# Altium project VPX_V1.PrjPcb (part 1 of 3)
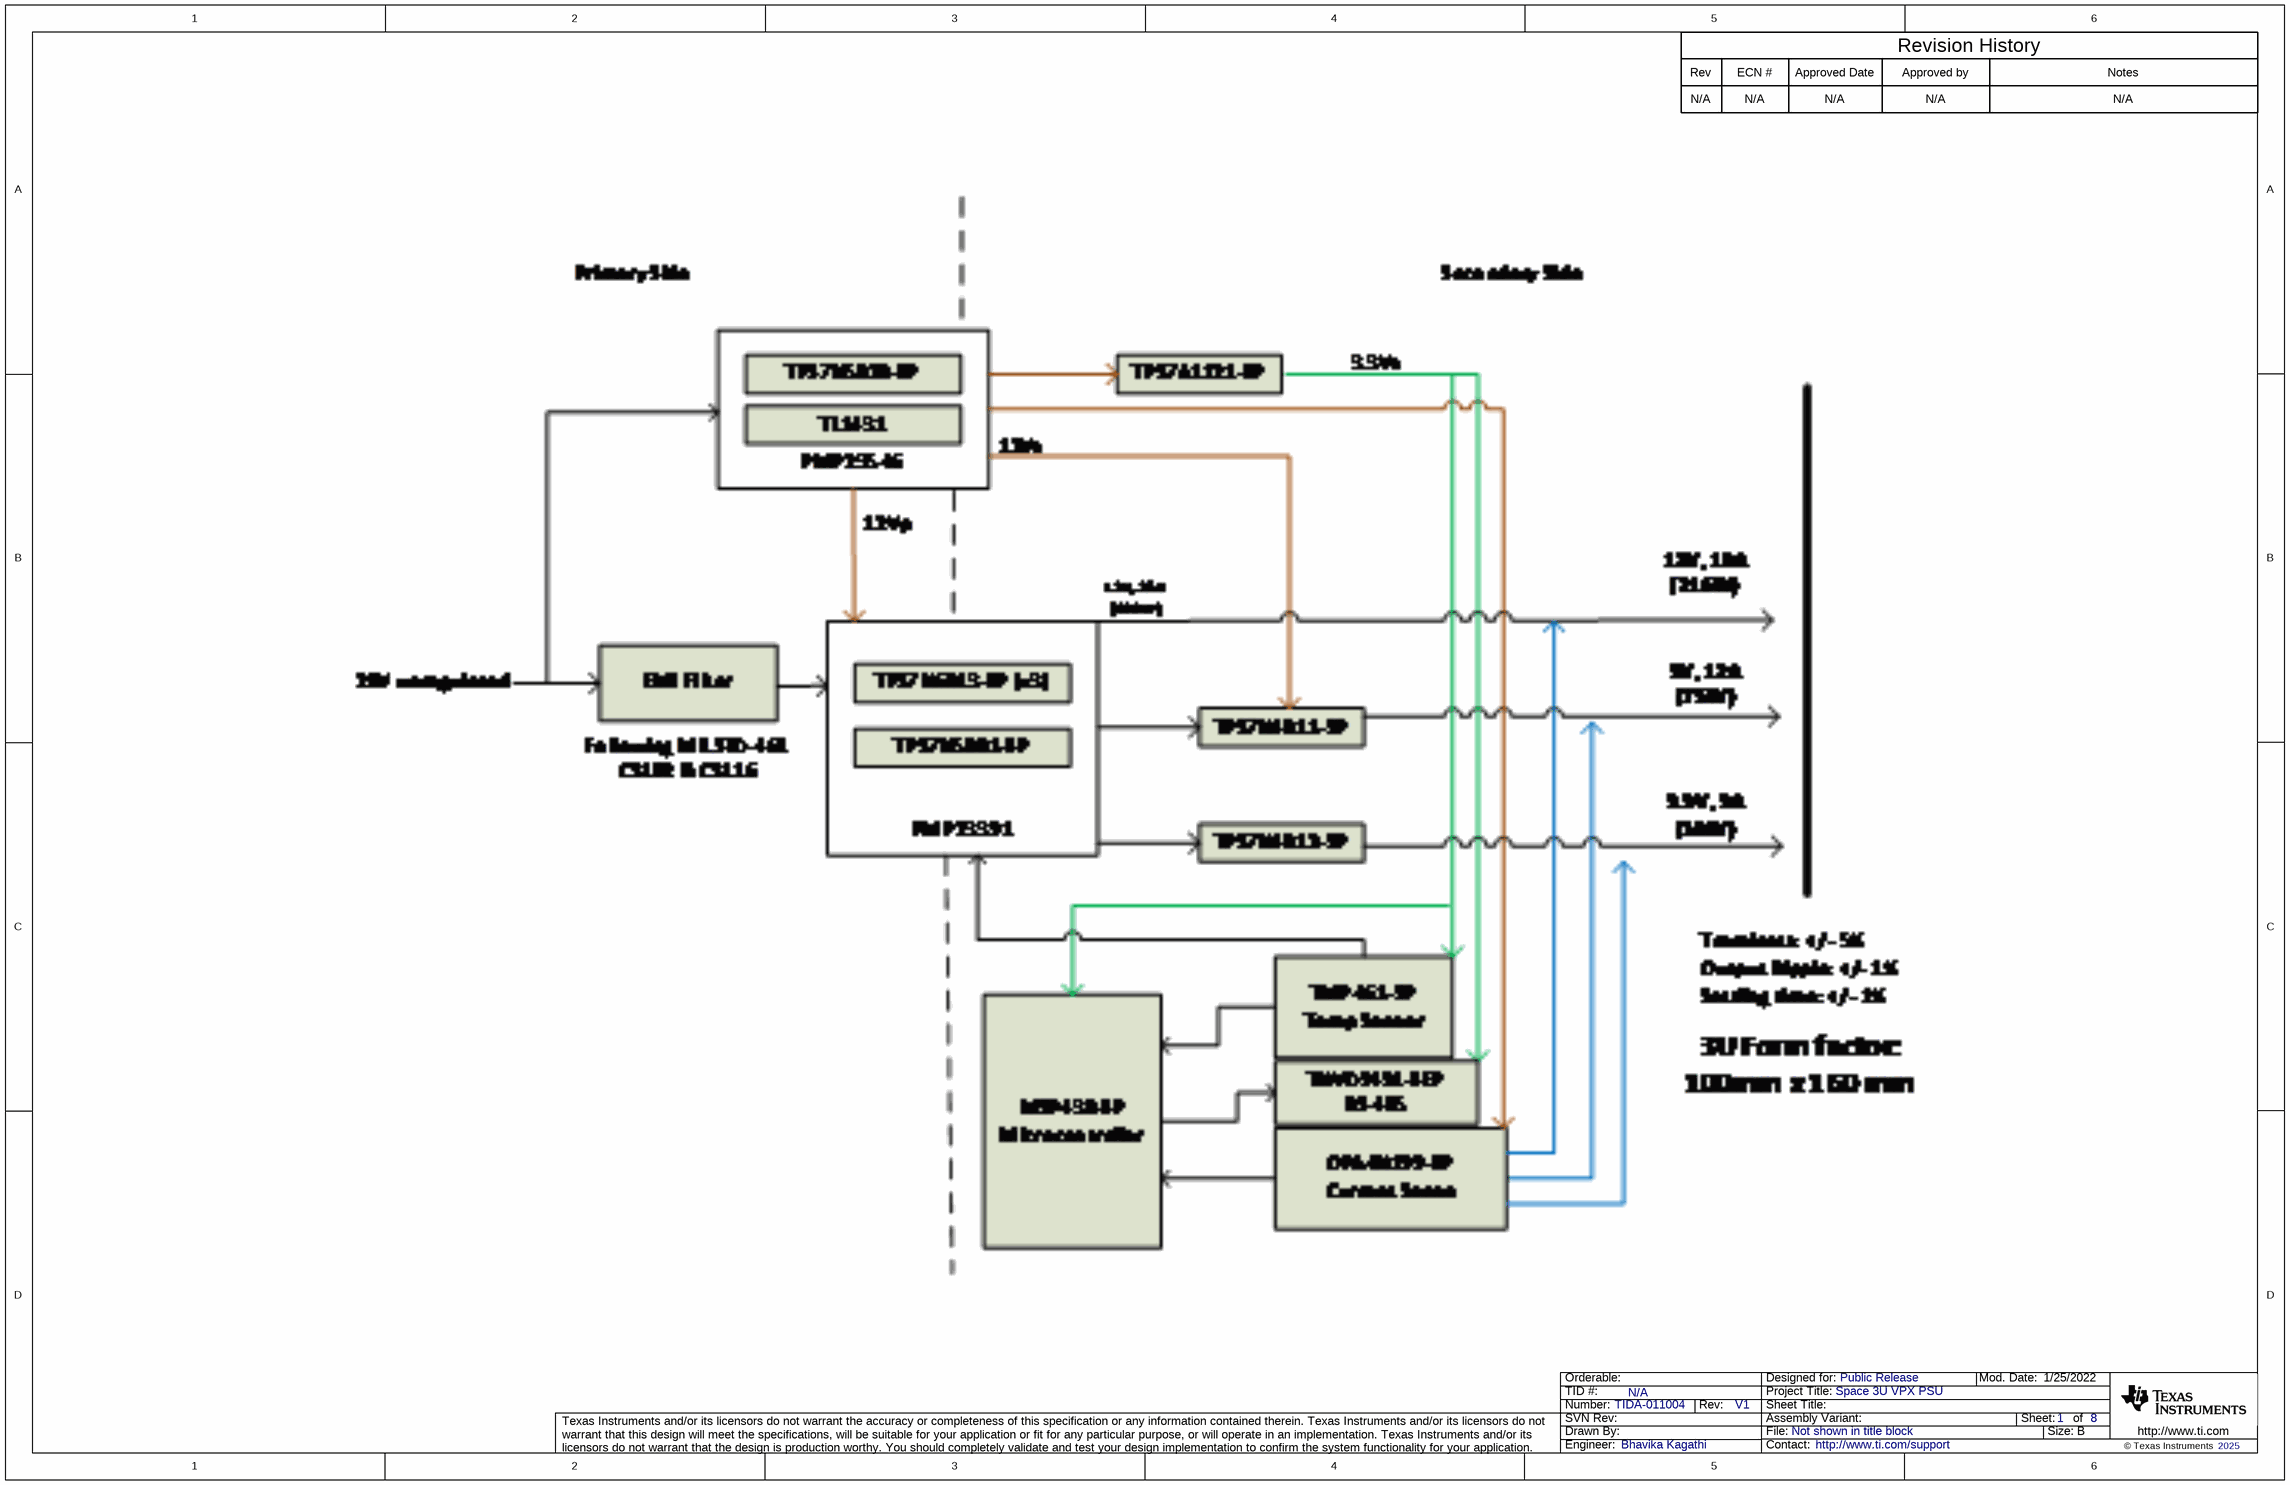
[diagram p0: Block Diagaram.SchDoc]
CopyrightYear: 2025; PCB_Rev: V1; PRJ_Customer: Public Release; PRJ_Engineer: Bhavika Kagathi; PRJ_Number: TIDA-011004; PRJ_Title: Space 3U VPX PSU; SCH_Rev: V1; Space 3U VPX PSU: Bhavika Kagathi; TechSupport: http://www.ti.com/support; TID: N/A
8 sheets, 383 parts. Net scope: flat (ports and power ports of the same name join across sheets).
Board file: VPX_V1.PcbDoc
Sheets:
  Block Diagaram.SchDoc
  12V Bias.SchDoc
  28V to 12 V.SchDoc
  28V to 12V drivers.SchDoc
  12V to 5V.SchDoc
  12 to 3.3V.SchDoc
  Telemetry.SchDoc
  Connector.SchDoc

## Sheet Block Diagaram.SchDoc
size 431 x 279 mm; Date: Not shown in title block; ApprovedBy: Not shown in title block; CheckedBy: Not shown in title block; Author: Not shown in title block; CompanyName: Not shown in title block; Engineer: Not shown in title block; Organization: Not shown in title block; Address1: Not shown in title block; Address2: Not shown in title block; Address3: Not shown in title block; Address4: Not shown in title block; DocumentNumber: 1; Revision: Use project parameter SCH_Rev; SheetNumber: 1; SheetTotal: 8; PageSetup: Record=PageOptions¦CenterHorizontal=True¦CenterVertical=True¦PrintScale=1.00¦XCorrection=1.00¦YCorrection=1.00¦PrintKind=0¦BorderSize=5000000¦LeftOffset=0¦BottomOffset=0¦Orientation=2¦PaperLength=1000¦PaperWidth=1000¦Scale=100¦PaperSource=15¦PrintQuality=600¦MediaType=1¦DitherType=10¦PaperKind=Letter¦PrintScaleMode=1

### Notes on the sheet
- Rev
- N/A
- ECN #
- Approved Date
- Approved by
- Revision History
- Notes

## Sheet 12V Bias.SchDoc
size 431 x 279 mm; Date: Not shown in title block; ApprovedBy: Not shown in title block; CheckedBy: Not shown in title block; Author: Not shown in title block; CompanyName: Not shown in title block; Engineer: Not shown in title block; Organization: Not shown in title block; Address1: Not shown in title block; Address2: Not shown in title block; Address3: Not shown in title block; Address4: Not shown in title block; DocumentNumber: 1; Revision: Use project parameter SCH_Rev; SheetNumber: 2; SheetTotal: 8; PageSetup: Record=PageOptions¦CenterHorizontal=True¦CenterVertical=True¦PrintScale=1.00¦XCorrection=1.00¦YCorrection=1.00¦PrintKind=0¦BorderSize=5000000¦LeftOffset=0¦BottomOffset=0¦Orientation=2¦PaperLength=1000¦PaperWidth=1000¦Scale=100¦PaperSource=15¦PrintQuality=600¦MediaType=1¦DitherType=10¦PaperKind=Letter¦PrintScaleMode=1
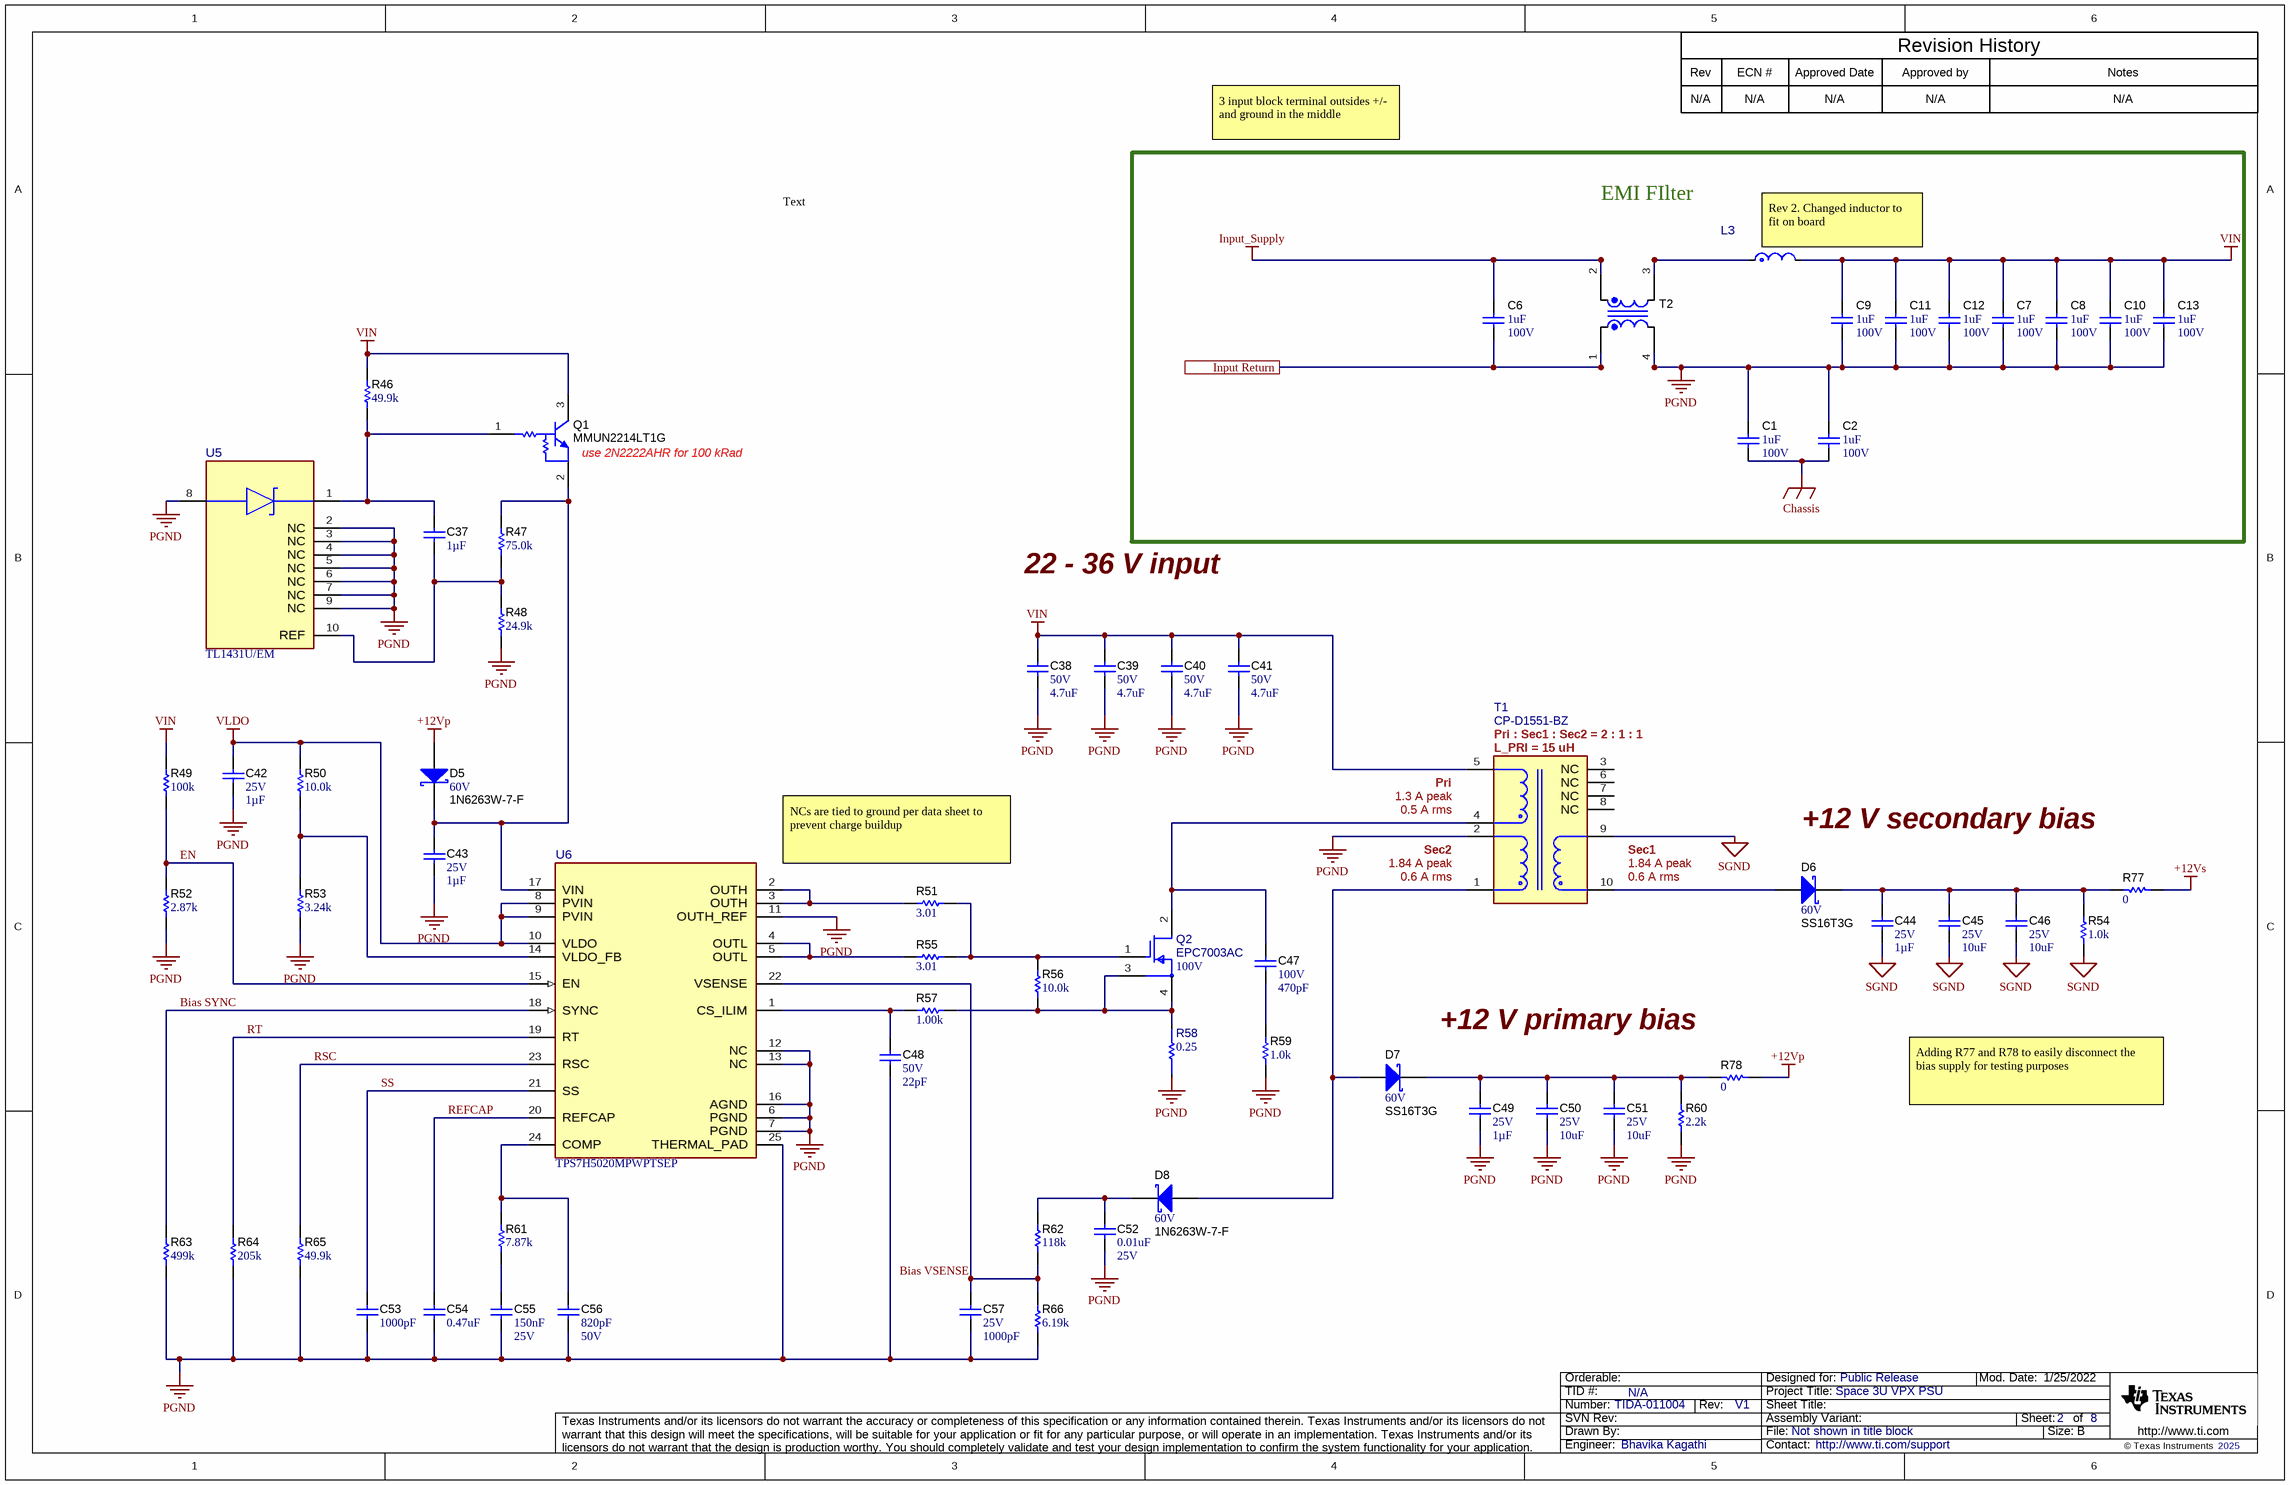
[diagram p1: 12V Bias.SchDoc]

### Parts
C1  ValueDisplayed: 1uF  VDC_V: 100V  [1210_270]  (hidden comment: GRM32ER72A105KA01L)
C2  ValueDisplayed: 1uF  VDC_V: 100V  [1210_270]  (hidden comment: GRM32ER72A105KA01L)
C6  ValueDisplayed: 1uF  VDC_V: 100V  [1210_270]  (hidden comment: GRM32ER72A105KA01L)
C7  ValueDisplayed: 1uF  VDC_V: 100V  [1210_270]  (hidden comment: GRM32ER72A105KA01L)
C8  ValueDisplayed: 1uF  VDC_V: 100V  [1210_270]  (hidden comment: GRM32ER72A105KA01L)
C9  ValueDisplayed: 1uF  VDC_V: 100V  [1210_270]  (hidden comment: GRM32ER72A105KA01L)
C10  ValueDisplayed: 1uF  VDC_V: 100V  [1210_270]  (hidden comment: GRM32ER72A105KA01L)
C11  ValueDisplayed: 1uF  VDC_V: 100V  [1210_270]  (hidden comment: GRM32ER72A105KA01L)
C12  ValueDisplayed: 1uF  VDC_V: 100V  [1210_270]  (hidden comment: GRM32ER72A105KA01L)
C13  ValueDisplayed: 1uF  VDC_V: 100V  [1210_270]  (hidden comment: GRM32ER72A105KA01L)
C37  Cap_F: 1µF  [0603]  (hidden comment: C0603C105K3RACTU)
C38  VDC_V: 50V  ValueDisplayed: 4.7uF  [0805_HV1]  (hidden comment: GRM21BR61H475KE51L)
C39  VDC_V: 50V  ValueDisplayed: 4.7uF  [0805_HV1]  (hidden comment: GRM21BR61H475KE51L)
C40  VDC_V: 50V  ValueDisplayed: 4.7uF  [0805_HV1]  (hidden comment: GRM21BR61H475KE51L)
C41  VDC_V: 50V  ValueDisplayed: 4.7uF  [0805_HV1]  (hidden comment: GRM21BR61H475KE51L)
C42  VDC_V: 25V  Cap_F: 1µF  [0603]  (hidden comment: C0603C105K3RACTU)
C43  VDC_V: 25V  Cap_F: 1µF  [0603]  (hidden comment: C0603C105K3RACTU)
C44  VDC_V: 25V  Cap_F: 1µF  [0603]  (hidden comment: C0603C105K3RACTU)
C45  VDC_V: 25V  ValueDisplayed: 10uF  [0805_HV1]  (hidden comment: GRM21BZ71E106KE15L)
C46  VDC_V: 25V  ValueDisplayed: 10uF  [0805_HV1]  (hidden comment: GRM21BZ71E106KE15L)
C47  VDC_V: 100V  ValueDisplayed: 470pF  [0603_HV]  (hidden comment: GRM1885C2A471JA01D)
C48  VDC_V: 50V  ValueDisplayed: 22pF  [0603_HV]  (hidden comment: GRM1885C1H220JA01D)
C49  VDC_V: 25V  Cap_F: 1µF  [0603]  (hidden comment: C0603C105K3RACTU)
C50  VDC_V: 25V  ValueDisplayed: 10uF  [0805_HV1]  (hidden comment: GRM21BZ71E106KE15L)
C51  VDC_V: 25V  ValueDisplayed: 10uF  [0805_HV1]  (hidden comment: GRM21BZ71E106KE15L)
C52  value 0.01uF  VDC_V: 25V  [0603_HV]  (hidden comment: GRM188R71E103KA01D)
C53  value 1000pF  [0603_HV]  (hidden comment: GRM188R71E102KA01D)
C54  value 0.47uF  [0603_HV]  (hidden comment: GCM188R71C474KA55D)
C55  Cap_F: 150nF  VDC_V: 25V  [0603_HV]  (hidden comment: GRM188R71E154KA01D)
C56  Cap_F: 820pF  VDC_V: 50V  [0603_HV]  (hidden comment: GRM188R71H821KA01D)
C57  value 1000pF  VDC_V: 25V  [0603_HV]  (hidden comment: GRM188R71E102KA01D)
D5  1N6263W-7-F  value 60V  [SOD-123]
D6  SS16T3G  value 60V  [SMA]
D7  SS16T3G  value 60V  [SMA]
D8  1N6263W-7-F  value 60V  [SOD-123]
L3  XGL1010-103MED  [FP-XGL1010-103MED_SMT_IND_10MM0_11MM3-MFG]  (value not drawn)
Q1  MMUN2214LT1G  [SOT-23]
Q2  EPC7003AC  VdsMax_V: 100V  [FP-EPC7003AC_FSMD-A-MFG]
R46  ValueDisplayed: 49.9k  [0603_HV]  (hidden comment: CRCW060349K9FKEA)
R47  ValueDisplayed: 75.0k  [0603_HV]  (hidden comment: CRCW060375K0FKEA)
R48  ValueDisplayed: 24.9k  [0603_HV]  (hidden comment: CRCW060324K9FKEA)
R49  ValueDisplayed: 100k  [0603_HV]  (hidden comment: CRCW0603100KFKEA)
R50  ValueDisplayed: 10.0k  [0603_HV]  (hidden comment: CRCW060310K0FKEA)
R51  ValueDisplayed: 3.01  [0603_HV]  (hidden comment: CRCW06033R01FKEA)
R52  ValueDisplayed: 2.87k  [0603_HV]  (hidden comment: CRCW06032K87FKEA)
R53  ValueDisplayed: 3.24k  [0603_HV]  (hidden comment: CRCW06033K24FKEA)
R54  ValueDisplayed: 1.0k  [1206]  (hidden comment: CRCW12061K00JNEA)
R55  ValueDisplayed: 3.01  [0603_HV]  (hidden comment: CRCW06033R01FKEA)
R56  ValueDisplayed: 10.0k  [0603_HV]  (hidden comment: CRCW060310K0FKEA)
R57  ValueDisplayed: 1.00k  [0603_HV]  (hidden comment: CRCW06031K00FKEA)
R58  ValueDisplayed: 0.25  [FP-CSR0805FKR250_0805-MFG]  (hidden comment: CSR0805FKR250)
R59  ValueDisplayed: 1.0k  [1210]  (hidden comment: RC1210JR-071KL)
R60  ValueDisplayed: 2.2k  [1206]  (hidden comment: CRCW12062K20JNEA)
R61  ValueDisplayed: 7.87k  [0603_HV]  (hidden comment: CRCW06037K87FKEA)
R62  ValueDisplayed: 118k  [0603_HV]  (hidden comment: CRCW0603118KFKEA)
R63  ValueDisplayed: 499k  [0603_HV]  (hidden comment: CRCW0603499KFKEA)
R64  ValueDisplayed: 205k  [0603_HV]  (hidden comment: CRCW0603205KFKEA)
R65  ValueDisplayed: 49.9k  [0603_HV]  (hidden comment: CRCW060349K9FKEA)
R66  ValueDisplayed: 6.19k  [0603_HV]  (hidden comment: CRCW06036K19FKEA)
R77  ValueDisplayed: 0  [0603_HV]  (hidden comment: CRCW06030000Z0EA)
R78  ValueDisplayed: 0  [0603_HV]  (hidden comment: CRCW06030000Z0EA)
T1  CP-D1551-BZ  [FP-CP-D1551-BZ_SMT_XFRMR_17MM75_14MM0-MFG]
T2  CM3440Z171R-10  [Laird_Z171R-10]  (value not drawn)
U5  TL1431U/EM  [NAC0010A-IPC_B]
U6  TPS7H5020MPWPTSEP  [PWP0024R-MFG]

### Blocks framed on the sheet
EMI FIlter: C1 C2 C6-C13 L3 T2

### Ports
Input Return

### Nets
+12Vp: D5.2(A) R78.2
+12Vs: R77.2
Chassis: C1.2 C2.2
Input_Supply: C6.1 T2.2
PGND: C1.1 C2.1 C7.2 C8.2 C9.2 C10.2 C11.2 C12.2 C13.2 C38.2 C39.2 C40.2 C41.2 C42.2 C43.2 C48.2 C49.2 C50.1 C51.1 C52.1 C53.1 C54.2 C55.2 C56.2 C57.1 R48.1 R52.1 R53.1 R58.1 R59.1 R60.1 R63.1 R64.1 R65.1 R66.1 T1.2 T2.4 U5.2(NC) U5.3(NC) U5.4(NC) U5.5(NC) U5.6(NC) U5.7(NC) U5.8(ANODE) U5.9(NC) U6.6(PGND) U6.7(PGND) U6.11(OUTH_REF) U6.12(NC) U6.13(NC) U6.16(AGND) U6.25(THERMAL_PAD)
SGND: C44.2 C45.1 C46.1 R54.1 T1.9
VIN: C7.1 C8.1 C9.1 C10.1 C11.1 C12.1 C13.1 C38.1 C39.1 C40.1 C41.1 L3.2 Q1.3(C) R46.2 R49.2 T1.5
VLDO: C42.1 R50.2 U6.8(PVIN) U6.9(PVIN) U6.10(VLDO)
Bias SYNC: R63.2 U6.18(SYNC)
Bias VSENSE: C57.2 R62.1 R66.2 U6.22(VSENSE)
EN: R49.1 R52.2 U6.15(EN)
Input Return: C6.2 T2.1 ; port Input Return
REFCAP: C54.1 U6.20(REFCAP)
RSC: R65.2 U6.23(RSC)
RT: R64.2 U6.19(RT)
SS: C53.2 U6.21(SS)
NetC37_1: C37.1 Q1.1(B) R46.1 U5.1(CATHODE)
NetC37_2: C37.2 R47.1 R48.2 U5.10(REF)
NetC43_1: C43.1 D5.1(K) Q1.2(E) R47.2 U6.17(VIN)
NetC44_1: C44.1 C45.2 C46.2 D6.1(K) R54.2 R77.1
NetC47_1: C47.1 Q2.2(D) T1.4
NetC47_2: C47.2 R59.2
NetC48_1: C48.1 R57.2 U6.1(CS_ILIM)
NetC49_1: C49.1 C50.2 C51.2 D7.1(K) R60.2 R78.1
NetC52_2: C52.2 D8.1(K) R62.2
NetC55_1: C55.1 R61.1
NetC56_1: C56.1 R61.2 U6.24(COMP)
NetD6_2: D6.2(A) T1.10
NetD7_2: D7.2(A) D8.2(A) T1.1
NetL3_1: L3.1 T2.3
NetQ2_1: Q2.1(G) R51.2 R55.2 R56.2
NetQ2_3: Q2.3(SS) Q2.4(S) R56.1 R57.1 R58.2
NetR50_1: R50.1 R53.2 U6.14(VLDO_FB)
NetR51_1: R51.1 U6.2(OUTH) U6.3(OUTH)
NetR55_1: R55.1 U6.4(OUTL) U6.5(OUTL)

Not connected (* = marked no-connect by the designer): T1 3(NC) 6(NC) 7(NC) 8(NC)

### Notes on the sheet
- Rev
- N/A
- ECN #
- Approved Date
- Approved by
- Revision History
- Notes
- 3 input block terminal outsides +/- and ground in the middle
- (near L3) Rev 2. Changed inductor to fit on board
- Text
- (near Q1) use 2N2222AHR for 100 kRad
- 22 - 36 V input
- (near T1) L_PRI = 15 uH
- (near T1) Pri : Sec1 : Sec2 = 2 : 1 : 1
- (near T1) Pri
- (near T1) 1.3 A peak
- (near T1) 0.5 A rms
- +12 V secondary bias
- NCs are tied to ground per data sheet to prevent charge buildup
- (near T1) Sec2
- (near T1) 1.84 A peak
- (near T1) 0.6 A rms
- (near T1) Sec1
- +12 V primary bias
- Adding R77 and R78 to easily disconnect the bias supply for testing purposes

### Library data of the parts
C1 C2 C6-C13 = CMP-0009231-2: CAP, CERM, 1 uF, 100 V, +/- 10%, X7R, 1210; Manufacturer: MuRata; Cap_F: 1µF; Value: 1uF; SizeZ_mm: 2.7; TaMin_C: -55°C; Polarized: N; SizeAreaWB_mm2: 14.7; Value1: Unknown; U/M: EA; TaMax_C: 125°C; SizeX_mm: 3.2; SizeY_mm: 2.5; Cap_Case: 1210; SizeArea_mm2: 8; AEC Category: Q200
C37 = CMP-0006867-4: CAP, CERM, 1 uF, 25 V, +/- 10%, X7R, 0603; Manufacturer: Kemet; VDC_V: 25V; AEC Category: Q200; Value: 1uF; SizeX_mm: 1.6; U/M: EA; Value1: Unknown; SizeAreaWB_mm2: 4.68; SizeY_mm: 0.8; TaMin_C: -55°C; SizeZ_mm: 1; Polarized: N; TaMax_C: 125°C; SizeArea_mm2: 1.28
C38-C41 = CMP-0008309-2: CAP, CERM, 4.7 uF, 50 V, +/- 10%, X5R, 0805; Manufacturer: MuRata; TaMin_C: -55°C; Polarized: N; SizeAreaWB_mm2: 6.75; Value1: Unknown; U/M: EA; Value: 4.7uF; TaMax_C: 85°C; SizeZ_mm: 1.45; SizeX_mm: 2; SizeY_mm: 1.25; Cap_Case: 0805; SizeArea_mm2: 2.5; Cap_F: 4.7µF; AEC Category: Q200
C42-C44 C49 = CMP-0006867-4: CAP, CERM, 1 uF, 25 V, +/- 10%, X7R, 0603; Manufacturer: Kemet; AEC Category: Q200; Value: 1uF; SizeX_mm: 1.6; U/M: EA; Value1: Unknown; SizeAreaWB_mm2: 4.68; SizeY_mm: 0.8; TaMin_C: -55°C; SizeZ_mm: 1; Polarized: N; TaMax_C: 125°C; SizeArea_mm2: 1.28
C45 C46 C50 C51 = CMP-0008378-2: CAP, CERM, 10 uF, 25 V, +/- 10%, X7R, 0805; Manufacturer: MuRata; TaMin_C: -55°C; Polarized: N; SizeAreaWB_mm2: 6.75; Value1: Unknown; U/M: EA; Value: 10uF; TaMax_C: 125°C; SizeZ_mm: 1.45; SizeX_mm: 2; SizeY_mm: 1.25; Cap_Case: 0805; SizeArea_mm2: 2.5; Cap_F: 10µF; AEC Category: Q200
C47 = CMP-0007272-4: CAP, CERM, 470 pF, 100 V, +/- 5%, C0G/NP0, 0603; Manufacturer: MuRata; TaMin_C: -55°C; Polarized: N; SizeAreaWB_mm2: 4.68; Value1: Unknown; U/M: EA; Value: 470pF; TaMax_C: 125°C; SizeZ_mm: 1; SizeX_mm: 1.6; SizeY_mm: 0.8; Cap_Case: 0603; SizeArea_mm2: 1.28; AEC Category: Q200
C48 = CMP-0007196-4: CAP, CERM, 22 pF, 50 V, +/- 5%, C0G/NP0, 0603; Manufacturer: MuRata; TaMin_C: -55°C; Polarized: N; SizeAreaWB_mm2: 4.68; Value1: Unknown; U/M: EA; Value: 22pF; TaMax_C: 125°C; SizeZ_mm: 1; SizeX_mm: 1.6; SizeY_mm: 0.8; Cap_Case: 0603; SizeArea_mm2: 1.28; AEC Category: Q200
C52 = CMP-0007403-4: CAP, CERM, 0.01 uF, 25 V, +/- 10%, X7R, 0603; Manufacturer: MuRata; TaMin_C: -55°C; Polarized: N; SizeAreaWB_mm2: 4.68; Value1: Unknown; U/M: EA; TaMax_C: 125°C; SizeZ_mm: 1; SizeX_mm: 1.6; SizeY_mm: 0.8; Cap_Case: 0603; SizeArea_mm2: 1.28; Cap_F: 10nF; AEC Category: Q200
C53 = CMP-0007402-5: CAP, CERM, 1000 pF, 25 V, +/- 10%, X7R, 0603; Manufacturer: MuRata; Value1: Unknown; VDC_V: 25V; TaMax_C: 125°C; Polarized: N; SizeArea_mm2: 1.28; Cap_Case: 0603; AEC Category: Q200; TaMin_C: -55°C; SizeX_mm: 1.6; U/M: EA; MFG_Status: TI_Obsolete; Cap_F: 1nF; SizeZ_mm: 1; SizeAreaWB_mm2: 4.68; SizeY_mm: 0.8
C54 = CMP-0007138-4: CAP, CERM, 0.47 uF, 16 V, +/- 10%, X7R, AEC-Q200 Grade 1, 0603; Manufacturer: MuRata; TaMin_C: -55°C; Polarized: N; SizeAreaWB_mm2: 4.68; Value1: Unknown; U/M: EA; TaMax_C: 125°C; SizeZ_mm: 1; SizeX_mm: 1.6; SizeY_mm: 0.8; Cap_Case: 0603; Value2: 16V; SizeArea_mm2: 1.28; AEC Qualified: Y; Cap_F: 470nF; AEC Category: Q200
C55 = CMP-0007411-4: CAP, CERM, 0.15 uF, 25 V, +/- 10%, X7R, 0603; Manufacturer: MuRata; TaMin_C: -55°C; Polarized: N; SizeAreaWB_mm2: 4.68; Value1: Unknown; U/M: EA; Value: 0.15uF; TaMax_C: 125°C; SizeZ_mm: 1; SizeX_mm: 1.6; SizeY_mm: 0.8; Cap_Case: 0603; SizeArea_mm2: 1.28; AEC Category: Q200
C56 = CMP-0007464-4: CAP, CERM, 820 pF, 50 V, +/- 10%, X7R, 0603; Manufacturer: MuRata; TaMin_C: -55°C; Polarized: N; SizeAreaWB_mm2: 4.68; Value1: Unknown; U/M: EA; Value: 820pF; TaMax_C: 125°C; SizeZ_mm: 1; SizeX_mm: 1.6; SizeY_mm: 0.8; Cap_Case: 0603; SizeArea_mm2: 1.28; AEC Category: Q200
C57 = CMP-0007402-5: CAP, CERM, 1000 pF, 25 V, +/- 10%, X7R, 0603; Manufacturer: MuRata; Value1: Unknown; TaMax_C: 125°C; Polarized: N; SizeArea_mm2: 1.28; Cap_Case: 0603; AEC Category: Q200; TaMin_C: -55°C; SizeX_mm: 1.6; U/M: EA; MFG_Status: TI_Obsolete; Cap_F: 1nF; SizeZ_mm: 1; SizeAreaWB_mm2: 4.68; SizeY_mm: 0.8
D5 D8 = CMP-0028361-2: Diode, Schottky, 60 V, 0.015 A, SOD-123; Manufacturer: Diodes Inc.; Green_REACh: Incomplete; Value1: 0.015A; Io_A: 15mA; SizeAreaWB_mm2: 13.095; AEC Category: Q101; Vf_V: 800mV; SizeZ_mm: 1.35; SizeX_mm: 3.85; SizeArea_mm2: 6.545; Value2: 0.8V; Green_Lifecycle: Not Set; SizeY_mm: 1.7
D6 D7 = CMP-0028585-2: Diode, Schottky, 60 V, 1 A, SMA; Manufacturer: ON Semiconductor; Green_REACh: Incomplete; Value2: 0.72V; SizeArea_mm2: 16.3228; SizeZ_mm: 2.87; Io_A: 1A; SizeX_mm: 5.59; Green_Lifecycle: Not Set; TJmax_C: 125°C; SizeAreaWB_mm2: 37.3428; RJC_CperW: 35; AEC Category: Q101; SizeY_mm: 2.92; Vf_V: 720mV
L3 = CMP-0120510-1: 10 µH Shielded Molded Inductor 18.2 A 9.7mOhm Max Nonstandard; Manufacturer: Coilcraft; Isat: 8.3A; Irms: 18.2A; DCR_ohm: 9.7m; Material: Composite; Value: 10uH; SizeZ_mm: 10mm; Ind_H: 10µH; AEC Qualified: Yes; AEC Grade: Grade 1; Self Resonant Frequency: 12MHz; Shrouded: true; TaMax_C: +125°C; TaMin_C: -40°C; Test Frequency: 1MHz; Tolerance_%: 20%
Q1 = CMP-0000511-2: Transistor, NPN, 50 V, 0.1 A, AEC-Q101, SOT-23; Manufacturer: ON Semiconductor; TaMax_C: 150°C; Value1: 0.1 A; Vcesat1_V: 250mV; SizeX_mm: 2.5; SizeY_mm: 3; TaMin_C: -55°C; IcRated_A: 100mA; CompType: BJT; SizeZ_mm: 1.1; AEC Qualified: Y; Value: 50 V; SizeArea_mm2: 7.5; NPN: 1; Vceo_V: 50V; PNP: 0; AEC Category: Q101; SizeAreaWB_mm2: 14; U/M: EA
Q2 = CMP-0041262-1: N-Channel 100 V 10A (Tc) Surface Mount 4-SMD; Manufacturer: EPC Space; AEC Qualified: No; QgTyp_nC: 1.5nC @ 5V; Rdson45_ohm: 42m; SizeZ_mm: 2.286mm; Vgs_V: 6V; ChMode: False; Input Capacitace At Vds: 168pF @ 50V; Number Of Channels: 1; Pulse Drain Current: 42A; Rthja Max: 62°C/W; Threshold Vgs Max: 2.5V; Threshold Vgs Min: 0.8V; TJmax_C: +150°C; Typ Forward Diode Voltage: 1.7V
R46 R65 = CMP-0022447-4: RES, 49.9 k, 1%, 0.1 W, AEC-Q200 Grade 0, 0603; Manufacturer: Vishay-Dale; Power_W: 100mW; TempCo: 100 ppm/C; Value_Code: 49k9; Value: 49.9k; EIA_Code: E96; SizeX_mm: 1.6; SizeY_mm: 0.8; SizeZ_mm: 1; Value2: 0.1W; SizeArea_mm2: 1.28; AEC Qualified: Y; VDC_V: 75V; AEC Category: Q200; AEC Grade: 0
R47 = CMP-0022589-4: RES, 75.0 k, 1%, 0.1 W, AEC-Q200 Grade 0, 0603; Manufacturer: Vishay-Dale; Power_W: 100mW; TempCo: 100 ppm/C; Value_Code: 75k0; Value: 75.0k; EIA_Code: E96; Res_ohm: 75k; SizeX_mm: 1.6; SizeY_mm: 0.8; SizeZ_mm: 1; Value2: 0.1W; SizeArea_mm2: 1.28; AEC Qualified: Y; VDC_V: 75V; AEC Category: Q200; AEC Grade: 0
R48 = CMP-0022237-4: RES, 24.9 k, 1%, 0.1 W, AEC-Q200 Grade 0, 0603; Manufacturer: Vishay-Dale; Power_W: 100mW; TempCo: 100 ppm/C; Value_Code: 24k9; Value: 24.9k; EIA_Code: E96; SizeX_mm: 1.6; SizeY_mm: 0.8; SizeZ_mm: 1; Value2: 0.1W; SizeArea_mm2: 1.28; AEC Qualified: Y; VDC_V: 75V; AEC Category: Q200; AEC Grade: 0
R49 = CMP-0021990-4: RES, 100 k, 1%, 0.1 W, AEC-Q200 Grade 0, 0603; Manufacturer: Vishay-Dale; Power_W: 100mW; TempCo: 100 ppm/C; Value: 100k; EIA_Code: E96; SizeX_mm: 1.6; SizeY_mm: 0.8; SizeZ_mm: 1; Value2: 0.1W; SizeArea_mm2: 1.28; AEC Qualified: Y; VDC_V: 75V; AEC Category: Q200; AEC Grade: 0
R50 R56 = CMP-0021998-4: RES, 10.0 k, 1%, 0.1 W, AEC-Q200 Grade 0, 0603; Manufacturer: Vishay-Dale; Power_W: 100mW; TempCo: 100 ppm/C; Value_Code: 10k0; Value: 10.0k; EIA_Code: E96; Res_ohm: 10k; SizeX_mm: 1.6; SizeY_mm: 0.8; SizeZ_mm: 1; Value2: 0.1W; SizeArea_mm2: 1.28; AEC Qualified: Y; VDC_V: 75V; AEC Category: Q200; AEC Grade: 0
R51 R55 = CMP-0022396-4: RES, 3.01, 1%, 0.1 W, AEC-Q200 Grade 0, 0603; Manufacturer: Vishay-Dale; Power_W: 100mW; TempCo: 100 ppm/C; Value_Code: 3R01; Value: 3.01; EIA_Code: E96; SizeX_mm: 1.6; SizeY_mm: 0.8; SizeZ_mm: 1; Value2: 0.1W; SizeArea_mm2: 1.28; AEC Qualified: Y; VDC_V: 75V; AEC Category: Q200; AEC Grade: 0
R52 = CMP-0022283-4: RES, 2.87 k, 1%, 0.1 W, AEC-Q200 Grade 0, 0603; Manufacturer: Vishay-Dale; Power_W: 100mW; TempCo: 100 ppm/C; Value_Code: 2k87; Value: 2.87k; EIA_Code: E96; SizeX_mm: 1.6; SizeY_mm: 0.8; SizeZ_mm: 1; Value2: 0.1W; SizeArea_mm2: 1.28; AEC Qualified: Y; VDC_V: 75V; AEC Category: Q200; AEC Grade: 0
R53 = CMP-0022374-4: RES, 3.24 k, 1%, 0.1 W, AEC-Q200 Grade 0, 0603; Manufacturer: Vishay-Dale; Power_W: 100mW; TempCo: 100 ppm/C; Value_Code: 3k24; Value: 3.24k; EIA_Code: E96; SizeX_mm: 1.6; SizeY_mm: 0.8; SizeZ_mm: 1; Value2: 0.1W; SizeArea_mm2: 1.28; AEC Qualified: Y; VDC_V: 75V; AEC Category: Q200; AEC Grade: 0
R54 = CMP-0018603-3: RES, 1.0 k, 5%, 0.25 W, AEC-Q200 Grade 0, 1206; Manufacturer: Vishay-Dale; Power_W: 250mW; TempCo: 200 ppm/C; Value_Code: 1k00; Value: 1.0k; EIA_Code: E24; Res_ohm: 1k; SizeX_mm: 3.2; SizeY_mm: 1.6; SizeZ_mm: 1.35; Value2: 0.25W; SizeArea_mm2: 5.12; AEC Qualified: Y; VDC_V: 200V; AEC Category: Q200; AEC Grade: 0
R57 = CMP-0022109-5: RES, 1.00 k, 1%, 0.1 W, AEC-Q200 Grade 0, 0603; Manufacturer: Vishay-Dale; Power_W: 100mW; TempCo: 100 ppm/C; Value_Code: 1k00; Value: 1.00k; EIA_Code: E96; Res_ohm: 1k; SizeX_mm: 1.6; SizeY_mm: 0.8; SizeZ_mm: 1; Value2: 0.1W; SizeArea_mm2: 1.28; AEC Qualified: Y; VDC_V: 75V; AEC Category: Q200; AEC Grade: 0
R58 = CMP-0088568-2: 250 mOhms ±1% 0.25W, 1/4W Chip Resistor 0805 (2012 Metric) Current Sense Thick Film; Manufacturer: Stackpole Electronics Inc; TempCo: 200ppm/°C; Power_W: 250mW; SizeZ_mm: 0.65mm; AEC Qualified: No
R59 = CMP-0083479-1: RES, 1.0 k, 5%, 0.5 W, 1210; Manufacturer: Yageo; Power_W: 500mW; TempCo: 100 ppm/C; SizeAreaWB_mm2: 14.7; Value_Code: 1k00; Value: 1.0k; EIA_Code: E24; Res_ohm: 1k; SizeX_mm: 3.2; SizeY_mm: 2.5; SizeZ_mm: 1.35; Value2: 0.5W; SizeArea_mm2: 8; AEC Qualified: N; VDC_V: 200V; AEC Category: Q200
R60 = CMP-0018641-3: RES, 2.2 k, 5%, 0.25 W, AEC-Q200 Grade 0, 1206; Manufacturer: Vishay-Dale; Power_W: 250mW; TempCo: 200 ppm/C; Value_Code: 2k20; Value: 2.2k; EIA_Code: E24; SizeX_mm: 3.2; SizeY_mm: 1.6; SizeZ_mm: 1.35; Value2: 0.25W; SizeArea_mm2: 5.12; AEC Qualified: Y; VDC_V: 200V; AEC Category: Q200; AEC Grade: 0
R61 = CMP-0022603-4: RES, 7.87 k, 1%, 0.1 W, AEC-Q200 Grade 0, 0603; Manufacturer: Vishay-Dale; Power_W: 100mW; TempCo: 100 ppm/C; Value_Code: 7k87; Value: 7.87k; EIA_Code: E96; SizeX_mm: 1.6; SizeY_mm: 0.8; SizeZ_mm: 1; Value2: 0.1W; SizeArea_mm2: 1.28; AEC Qualified: Y; VDC_V: 75V; AEC Category: Q200; AEC Grade: 0
R62 = CMP-0022014-4: RES, 118 k, 1%, 0.1 W, AEC-Q200 Grade 0, 0603; Manufacturer: Vishay-Dale; Power_W: 100mW; TempCo: 100 ppm/C; Value: 118k; EIA_Code: E96; SizeX_mm: 1.6; SizeY_mm: 0.8; SizeZ_mm: 1; Value2: 0.1W; SizeArea_mm2: 1.28; AEC Qualified: Y; VDC_V: 75V; AEC Category: Q200; AEC Grade: 0
R63 = CMP-0022445-4: RES, 499 k, 1%, 0.1 W, AEC-Q200 Grade 0, 0603; Manufacturer: Vishay-Dale; Power_W: 100mW; TempCo: 100 ppm/C; Value: 499k; EIA_Code: E96; SizeX_mm: 1.6; SizeY_mm: 0.8; SizeZ_mm: 1; Value2: 0.1W; SizeArea_mm2: 1.28; AEC Qualified: Y; VDC_V: 75V; AEC Category: Q200; AEC Grade: 0
R64 = CMP-0022202-4: RES, 205 k, 1%, 0.1 W, AEC-Q200 Grade 0, 0603; Manufacturer: Vishay-Dale; Power_W: 100mW; TempCo: 100 ppm/C; Value: 205k; EIA_Code: E96; SizeX_mm: 1.6; SizeY_mm: 0.8; SizeZ_mm: 1; Value2: 0.1W; SizeArea_mm2: 1.28; AEC Qualified: Y; VDC_V: 75V; AEC Category: Q200; AEC Grade: 0
R66 = CMP-0022559-4: RES, 6.19 k, 1%, 0.1 W, AEC-Q200 Grade 0, 0603; Manufacturer: Vishay-Dale; Power_W: 100mW; TempCo: 100 ppm/C; Value_Code: 6k19; Value: 6.19k; EIA_Code: E96; SizeX_mm: 1.6; SizeY_mm: 0.8; SizeZ_mm: 1; Value2: 0.1W; SizeArea_mm2: 1.28; AEC Qualified: Y; VDC_V: 75V; AEC Category: Q200; AEC Grade: 0
R77 R78 = CMP-0025697-4: RES, 0, 5%, 0.1 W, AEC-Q200 Grade 0, 0603; Manufacturer: Vishay-Dale; Power_W: 100mW; TempCo: 200 ppm/C; Value_Code: 0000; Value: 0; EIA_Code: E24; SizeX_mm: 1.6; SizeY_mm: 0.8; SizeZ_mm: 1; Value2: 0.1W; SizeArea_mm2: 1.28; AEC Qualified: Y; VDC_V: 75V; AEC Category: Q200
T1 = CMP-0123192-1: Transformer; Manufacturer: Coilcraft; Ind_H: 18µH; Ns1toNp: 1:0.5:0.5; SizeZ_mm: 12.32mm; AEC Qualified: No; Frequency_Fixed: 500kHz; Voltage_Isolation_Vrms: 2500Vrms
T2 = CMP-0081219-1: Coupled inductor, 0.001 ohm, AEC-Q200 Grade 1, SMD; Manufacturer: Laird-Signal Integrity Products; SizeAreaWB_mm2: 137.1555; DCR_ohm: 1m; SizeZ_mm: 10.49; SizeX_mm: 11.05; SizeY_mm: 8.51; SizeArea_mm2: 94.0355; AEC Qualified: Y; AEC Category: Q200; AEC Grade: 1
U5 = CMP-0093806-3: Radiation-hardness-assured (RHA) 0.4% accuracy, 2.4-V to 36-V adjustable shunt reference 10-CFP 25 to 25; Manufacturer: Texas Instruments; Number Of Outputs: 1; TaMax_C: +125°C; AEC Qualified: No; AEC Category: Q200; Output Type: AdjustableProgrammable; TJmax_C: +150°C; Max Supply Voltage: 36V; Output Voltage: 2.5-36V; Min Supply Voltage: 2.475V; CompType: IC; TaMin_C: -55°C
U6 = CMP-0122233-2: Radiation-Hardness-Assured 1-MHz Current Mode PWM Controller with Integrated Gate Driver; Manufacturer: Texas Instruments; SizeZ_mm: 1.2mm; AEC Qualified: No; Max Supply Voltage: 14V; Min Supply Voltage: 4.5V; Nominal Supply Current: 5-22mA; Number Of Outputs: 1; Standoff Height: 0.05mm; TJmax_C: +125°C; AEC Category: Q200; CompType: IC

## Sheet 28V to 12 V.SchDoc
size 431 x 279 mm; Date: Not shown in title block; ApprovedBy: Not shown in title block; CheckedBy: Not shown in title block; Author: Not shown in title block; CompanyName: Not shown in title block; Engineer: Not shown in title block; Organization: Not shown in title block; Address1: Not shown in title block; Address2: Not shown in title block; Address3: Not shown in title block; Address4: Not shown in title block; DocumentNumber: 1; Revision: Use project parameter SCH_Rev; SheetNumber: 3; SheetTotal: 8; PageSetup: Record=PageOptions¦CenterHorizontal=True¦CenterVertical=True¦PrintScale=1.00¦XCorrection=1.00¦YCorrection=1.00¦PrintKind=0¦BorderSize=5000000¦LeftOffset=0¦BottomOffset=0¦Orientation=2¦PaperLength=1000¦PaperWidth=1000¦Scale=100¦PaperSource=15¦PrintQuality=600¦MediaType=1¦DitherType=10¦PaperKind=Letter¦PrintScaleMode=1
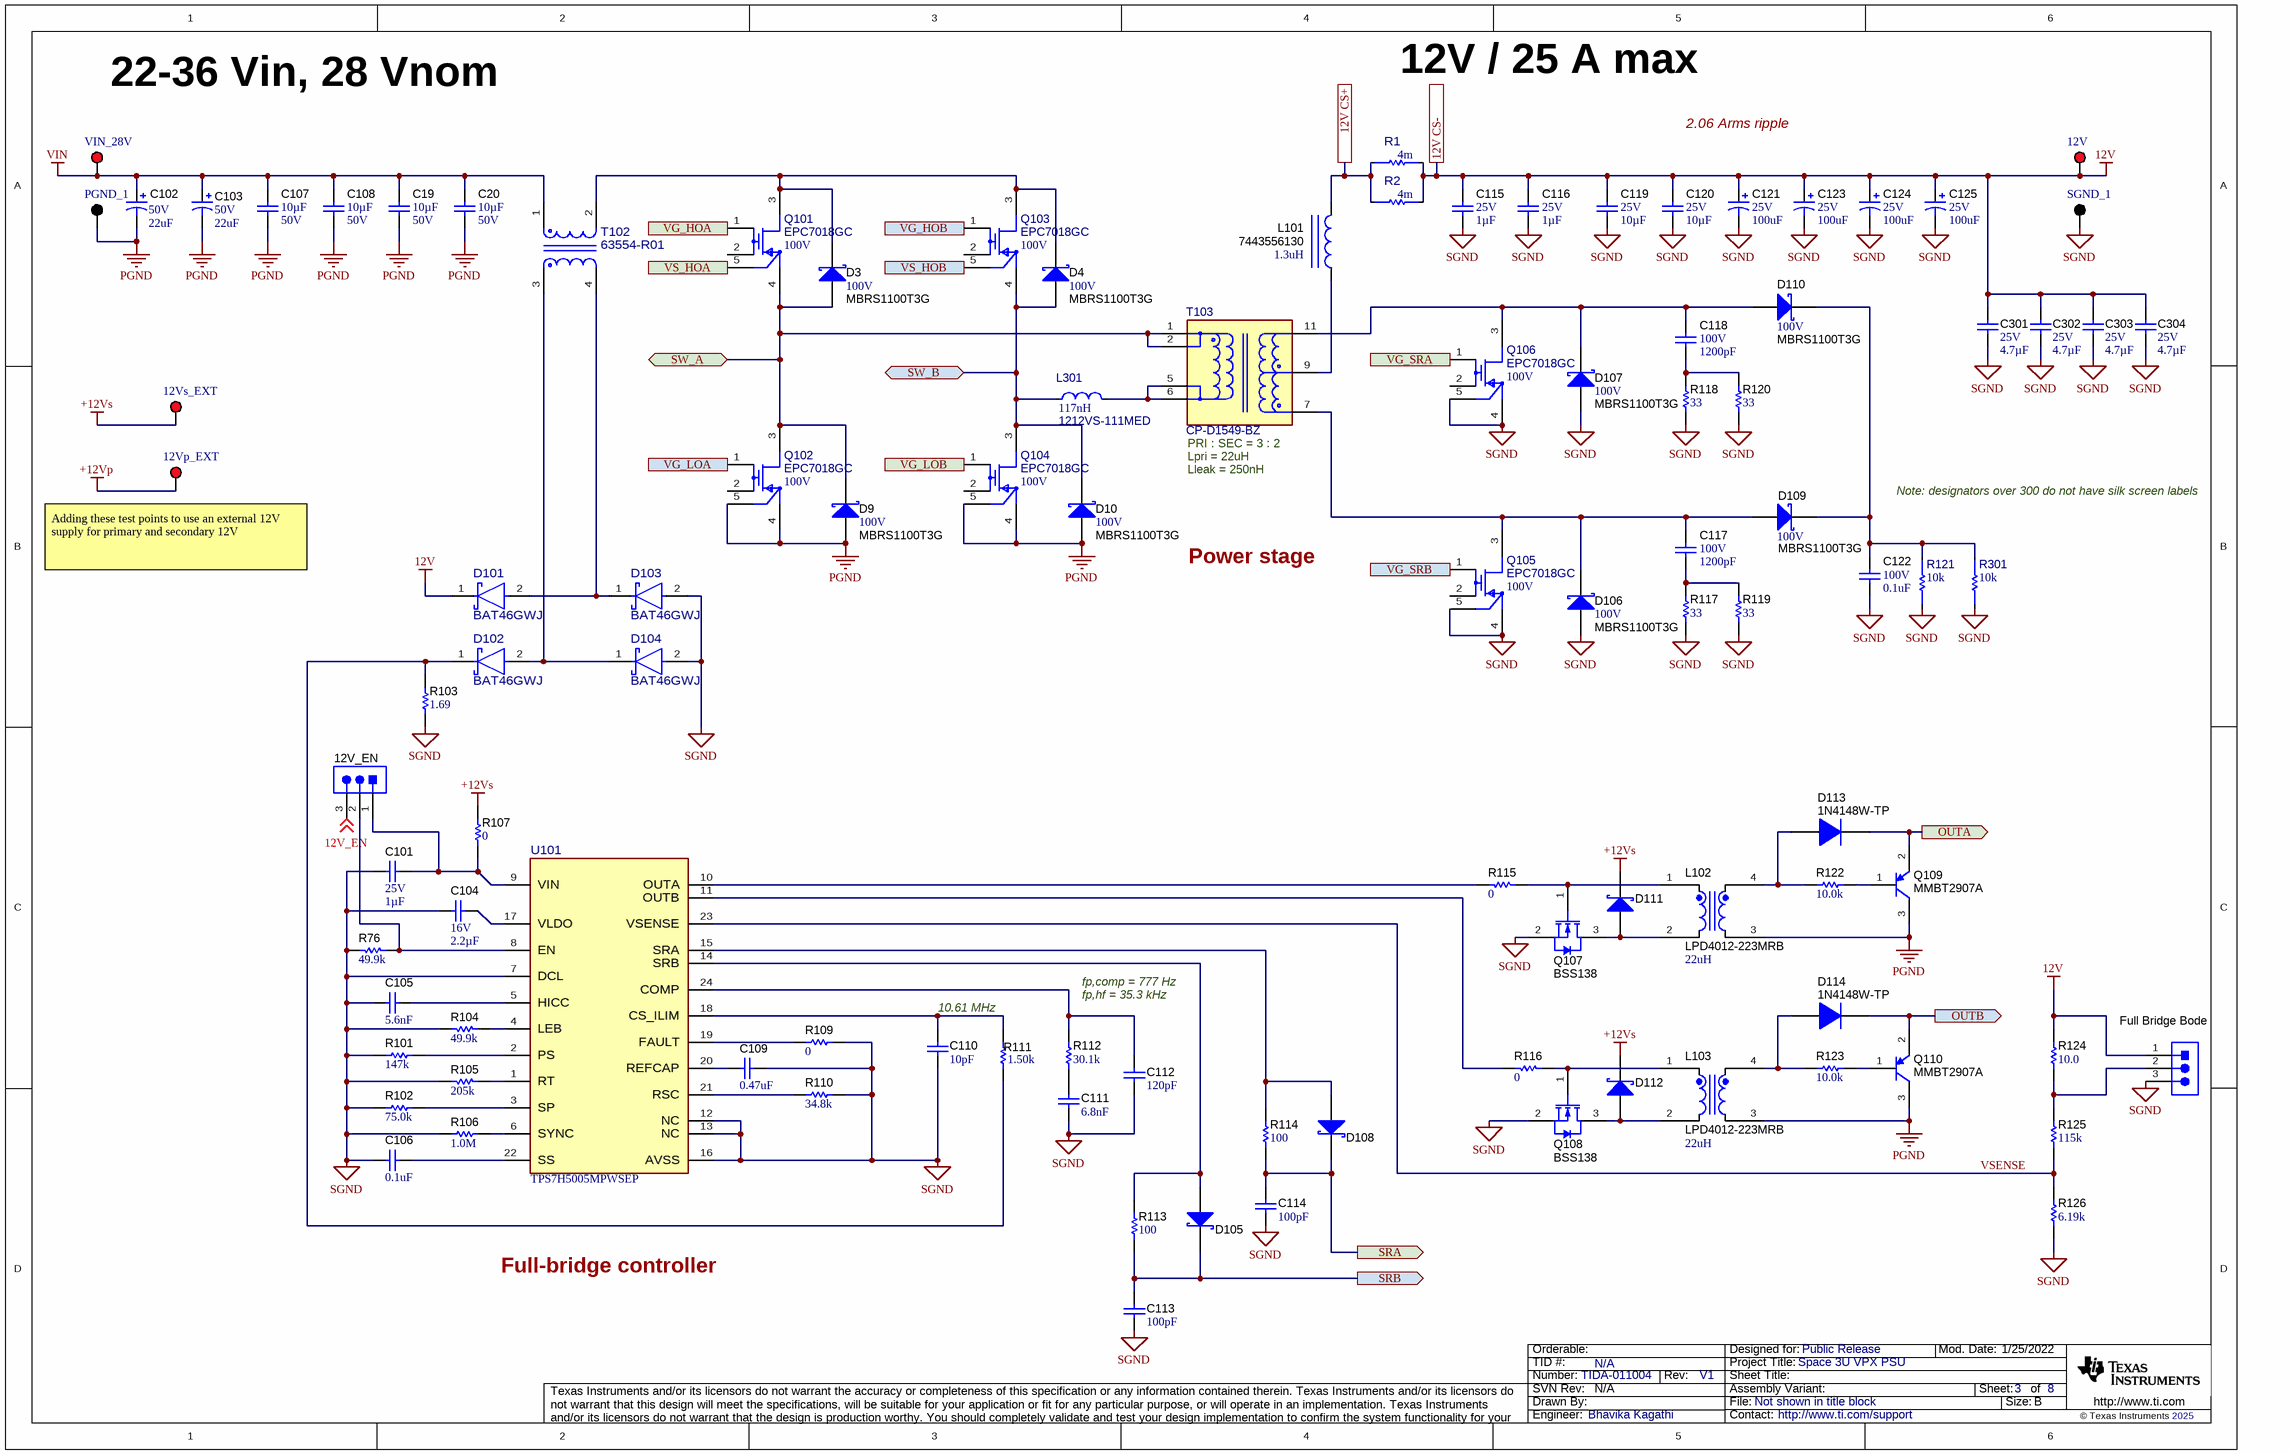
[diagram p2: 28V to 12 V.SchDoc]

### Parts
12V  5010  [Keystone5010]  (value not drawn)
12V_EN  PTT-103-01-L-S  [Samtec_PTT-103-01-x-S]  (value not drawn)
12Vp_EXT  5010  [Keystone5010]  (value not drawn)
12Vs_EXT  5010  [Keystone5010]  (value not drawn)
C19  ValueDisplayed: 10µF  VDC_V: 50V  [1210_270]  (hidden comment: GCM32EL8EH106KA07L)
C20  ValueDisplayed: 10µF  VDC_V: 50V  [1210_270]  (hidden comment: GCM32EL8EH106KA07L)
C101  VDC_V: 25V  Cap_F: 1µF  [0603_HV]  (hidden comment: GRM188R71E105KA12D)
C102  VDC_V: 50V  ValueDisplayed: 22uF  [7343-43]  (hidden comment: T494X226K050AT)
C103  VDC_V: 50V  ValueDisplayed: 22uF  [7343-43]  (hidden comment: T494X226K050AT)
C104  VDC_V: 16V  Cap_F: 2.2µF  [0603_HV]  (hidden comment: GRM188Z71C225KE43)
C105  Cap_F: 5.6nF  [0603_HV]  (hidden comment: GRM188R71E562KA01D)
C106  value 0.1uF  [0603_HV]  (hidden comment: GCM188R71E104KA57D)
C107  ValueDisplayed: 10µF  VDC_V: 50V  [1210_270]  (hidden comment: GCM32EL8EH106KA07L)
C108  ValueDisplayed: 10µF  VDC_V: 50V  [1210_270]  (hidden comment: GCM32EL8EH106KA07L)
C109  value 0.47uF  [0603_HV]  (hidden comment: GCM188R71C474KA55D)
C110  ValueDisplayed: 10pF  [0603_HV]  (hidden comment: GCM1885C2A100JA16D)
C111  Cap_F: 6.8nF  [0603L]  (hidden comment: GRM188R71E682KA01D)
C112  ValueDisplayed: 120pF  [0603_HV]  (hidden comment: GRM1885C1H121JA01D)
C113  ValueDisplayed: 100pF  [0603_HV]  (hidden comment: GRM1885C1H101JA01D)
C114  ValueDisplayed: 100pF  [0603_HV]  (hidden comment: GRM1885C1H101JA01D)
C115  VDC_V: 25V  Cap_F: 1µF  [0603_HV]  (hidden comment: GRM188R71E105KA12D)
C116  VDC_V: 25V  Cap_F: 1µF  [0603_HV]  (hidden comment: GRM188R71E105KA12D)
C117  VDC_V: 100V  ValueDisplayed: 1200pF  [0805L]  (hidden comment: GRM2165C2A122JA01D)
C118  VDC_V: 100V  ValueDisplayed: 1200pF  [0805_HV]  (hidden comment: GRM2165C2A122JA01D)
C119  VDC_V: 25V  ValueDisplayed: 10µF  [1206]  (hidden comment: GRM31CR71E106MA12L)
C120  VDC_V: 25V  ValueDisplayed: 10µF  [1206]  (hidden comment: GRM31CR71E106MA12L)
C121  VDC_V: 25V  ValueDisplayed: 100uF  [7361-38]  (hidden comment: TPSV107K025R0100)
C122  VDC_V: 100V  ValueDisplayed: 0.1uF  [1206]  (hidden comment: GRM319R72A104KA01D)
C123  VDC_V: 25V  ValueDisplayed: 100uF  [7361-38]  (hidden comment: TPSV107K025R0100)
C124  VDC_V: 25V  ValueDisplayed: 100uF  [7361-38]  (hidden comment: TPSV107K025R0100)
C125  VDC_V: 25V  ValueDisplayed: 100uF  [7361-38]  (hidden comment: TPSV107K025R0100)
C301  VDC_V: 25V  Cap_F: 4.7µF  [0805_HV]  (hidden comment: GRM21BR71E475KA73L)
C302  VDC_V: 25V  Cap_F: 4.7µF  [0805_HV]  (hidden comment: GRM21BR71E475KA73L)
C303  VDC_V: 25V  Cap_F: 4.7µF  [0805_HV]  (hidden comment: GRM21BR71E475KA73L)
C304  VDC_V: 25V  Cap_F: 4.7µF  [0805_HV]  (hidden comment: GRM21BR71E475KA73L)
D3  MBRS1100T3G  value 100V  [SMB]
D4  MBRS1100T3G  value 100V  [SMB]
D9  MBRS1100T3G  value 100V  [SMB]
D10  MBRS1100T3G  value 100V  [SMB]
D101  BAT46GWJ  [FP-BAT46GWJ_SOD-123-MFG]
D102  BAT46GWJ  [FP-BAT46GWJ_SOD-123-MFG]
D103  BAT46GWJ  [FP-BAT46GWJ_SOD-123-MFG]
D104  BAT46GWJ  [FP-BAT46GWJ_SOD-123-MFG]
D105  PMEG4030ER,115  [SOD-123W]  (value not drawn)
D106  MBRS1100T3G  value 100V  [SMB]
D107  MBRS1100T3G  value 100V  [SMB]
D108  PMEG4030ER,115  [SOD-123W]  (value not drawn)
D109  MBRS1100T3G  value 100V  [SMB]
D110  MBRS1100T3G  value 100V  [SMB]
D111  PMEG4030ER,115  [SOD-123W]  (value not drawn)
D112  PMEG4030ER,115  [SOD-123W]  (value not drawn)
D113  1N4148W-TP  [SOD-123]
D114  1N4148W-TP  [SOD-123]
Full_Bridge_Bode  PTT-103-01-L-S  [Samtec_PTT-103-01-x-S]  (value not drawn)
L101  7443556130  ValueDisplayed: 1.3uH  [WE-HCB_1890]
L102  LPD4012-223MRB  ValueDisplayed: 22uH  [LPD4012]
L103  LPD4012-223MRB  ValueDisplayed: 22uH  [LPD4012]
L301  1212VS-111MED  value 117nH  [FP-1212VS-111MED_SMT_IND_11MM5_12MM0-MFG]
PGND_1  5011  [Keystone5011]  (value not drawn)
Q101  EPC7018GC  VdsMax_V: 100V  [FP-EPC7018GC_FSMD-G-MFG]
Q102  EPC7018GC  VdsMax_V: 100V  [FP-EPC7018GC_FSMD-G-MFG]
Q103  EPC7018GC  VdsMax_V: 100V  [FP-EPC7018GC_FSMD-G-MFG]
Q104  EPC7018GC  VdsMax_V: 100V  [FP-EPC7018GC_FSMD-G-MFG]
Q105  EPC7018GC  VdsMax_V: 100V  [FP-EPC7018GC_FSMD-G-MFG]
Q106  EPC7018GC  VdsMax_V: 100V  [FP-EPC7018GC_FSMD-G-MFG]
Q107  BSS138  [SOT-23]
Q108  BSS138  [SOT-23]
Q109  MMBT2907A  [SOT-23]
Q110  MMBT2907A  [SOT-23]
R1  value 4m  [FP-KRL2012E-M-R004-F-T5_2012-MFG]  (hidden comment: KRL2012E-M-R004-F-T5)
R2  value 4m  [FP-KRL2012E-M-R004-F-T5_2012-MFG]  (hidden comment: KRL2012E-M-R004-F-T5)
R76  ValueDisplayed: 49.9k  [0603_HV]  (hidden comment: CRCW060349K9FKEA)
R101  ValueDisplayed: 147k  [0603_HV]  (hidden comment: CRCW0603147KFKEA)
R102  ValueDisplayed: 75.0k  [0603_HV]  (hidden comment: CRCW060375K0FKEA)
R103  ValueDisplayed: 1.69  [1206]  (hidden comment: CRCW12061R69FKEA)
R104  ValueDisplayed: 49.9k  [0603_HV]  (hidden comment: CRCW060349K9FKEA)
R105  ValueDisplayed: 205k  [0603_HV]  (hidden comment: RC0603FR-07205KL)
R106  ValueDisplayed: 1.0M  [0603_HV]  (hidden comment: CRCW06031M00JNEA)
R107  ValueDisplayed: 0  [0603_HV]  (hidden comment: CRCW06030000Z0EA)
R109  ValueDisplayed: 0  [0603_HV]  (hidden comment: CRCW06030000Z0EA)
R110  ValueDisplayed: 34.8k  [0603_HV]  (hidden comment: CRCW060334K8FKEA)
R111  ValueDisplayed: 1.50k  [0603_HV]  (hidden comment: CRCW06031K50FKEA)
R112  ValueDisplayed: 30.1k  [0603_HV]  (hidden comment: CRCW060330K1FKEA)
R113  ValueDisplayed: 100  [0603_HV]  (hidden comment: CRCW0603100RJNEA)
R114  ValueDisplayed: 100  [0603_HV]  (hidden comment: CRCW0603100RJNEA)
R115  ValueDisplayed: 0  [0805_HV1]  (hidden comment: RC0805JR-070RL)
R116  ValueDisplayed: 0  [0805_HV1]  (hidden comment: RC0805JR-070RL)
R117  ValueDisplayed: 33  [2512]  (hidden comment: CRCW251233R0JNEG)
R118  ValueDisplayed: 33  [2512]  (hidden comment: CRCW251233R0JNEG)
R119  ValueDisplayed: 33  [2512]  (hidden comment: CRCW251233R0JNEG)
R120  ValueDisplayed: 33  [2512]  (hidden comment: CRCW251233R0JNEG)
R121  value 10k  [FP-CRM2512-FX-1002ELF_2512-MFG]  (hidden comment: CRM2512-FX-1002ELF)
R122  ValueDisplayed: 10.0k  [0603_HV]  (hidden comment: CRCW060310K0FKEA)
R123  ValueDisplayed: 10.0k  [0603_HV]  (hidden comment: CRCW060310K0FKEA)
R124  ValueDisplayed: 10.0  [0603_HV]  (hidden comment: CRCW060310R0FKEA)
R125  ValueDisplayed: 115k  [0603_HV]  (hidden comment: CRCW0603115KFKEA)
R126  ValueDisplayed: 6.19k  [0603_HV]  (hidden comment: CRCW06036K19FKEA)
R301  value 10k  [FP-CRM2512-FX-1002ELF_2512-MFG]  (hidden comment: CRM2512-FX-1002ELF)
SGND_1  5011  [Keystone5011]  (value not drawn)
T102  63554-R01  [FP-63554-R01_SMT_XFRMR_24MM0_20MM0-MFG]
T103  CP-D1549-BZ  [FP-CP-D1549-BZ_SMT_XFRMR_29MM46_26MM67-MFG]
U101  TPS7H5005MPWSEP  [PW0024A-MFG]
VIN_28V  5010  [Keystone5010]  (value not drawn)

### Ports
12V CS+, 12V CS-, OUTA (out), OUTB (out), SRA (out), SRB (out), SW_A (bidir), SW_B (bidir), VG_HOA (in), VG_HOB (in), VG_LOA (in), VG_LOB (in), VG_SRA (in), VG_SRB (in), VS_HOA (in), VS_HOB (in)

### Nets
12V: 12V.1 C115.1 C116.1 C119.1 C120.1 C121.1(+) C123.1(+) C124.1(+) C125.1(+) C301.1 C302.1 C303.1 C304.1 D101.1(CATHODE) Full_Bridge_Bode.1 R1.2 R2.2 R124.2 ; port 12V CS-  [project net PVIN]
+12Vp: 12Vp_EXT.1
+12Vs: 12Vs_EXT.1 D111.1(K) D112.1(K) R107.2
PGND: C19.2 C20.2 C102.2(-) C103.2(-) C107.2 C108.2 D9.2(A) D10.2(A) L102.3 L103.3 PGND_1.1 Q102.4(S) Q102.5(SS) Q104.4(S) Q104.5(SS) Q109.3(C) Q110.3(C)
SGND: C101.2 C104.1 C105.1 C106.2 C109.1 C110.2 C111.2 C112.2 C113.1 C114.1 C115.2 C116.2 C119.2 C120.2 C121.2(-) C122.2 C123.2(-) C124.2(-) C125.2(-) C301.2 C302.2 C303.2 C304.2 D103.2(ANODE) D104.2(ANODE) D106.2(A) D107.2(A) Full_Bridge_Bode.3 Q105.4(S) Q105.5(SS) Q106.4(S) Q106.5(SS) Q107.2(S) Q108.2(S) R76.2 R101.1 R102.1 R103.1 R104.2 R105.2 R106.1 R109.2 R110.2 R117.1 R118.1 R119.1 R120.1 R121.2 R126.1 R301.2 SGND_1.1 U101.7(DCL) U101.12(NC) U101.13(NC) U101.16(AVSS)
VIN: C19.1 C20.1 C102.1(+) C103.1(+) C107.1 C108.1 T102.1 VIN_28V.1
12V CS+: L101.2 R1.1 R2.1 ; port 12V CS+
12V_EN: 12V_EN.3 ; off-sheet 12V_EN
OUTA: D113.1(K) Q109.2(E) ; port OUTA
OUTB: D114.1(K) Q110.2(E) ; port OUTB
SRA: C114.2 D108.1(K) R114.1 ; port SRA
SRB: C113.2 D105.1(K) R113.1 ; port SRB
SW_A: D3.2(A) D9.1(K) Q101.4(S) Q102.3(D) T103.1 T103.2 ; port SW_A
SW_B: D4.2(A) D10.1(K) L301.1 Q103.4(S) Q104.3(D) ; port SW_B
VG_HOA: Q101.1(G) ; port VG_HOA
VG_HOB: Q103.1(G) ; port VG_HOB
VG_LOA: Q102.1(G) ; port VG_LOA
VG_LOB: Q104.1(G) ; port VG_LOB
VG_SRA: Q106.1(G) ; port VG_SRA
VG_SRB: Q105.1(G) ; port VG_SRB
VS_HOA: Q101.5(SS) ; port VS_HOA
VS_HOB: Q103.5(SS) ; port VS_HOB
VSENSE: R125.1 R126.2 U101.23(VSENSE)
Net12V_EN_1: 12V_EN.1 C101.1 R107.1 U101.9(VIN)
Net12V_EN_2: 12V_EN.2 R76.1 U101.8(EN)
NetC104_2: C104.2 U101.17(VLDO)
NetC105_2: C105.2 U101.5(HICC)
NetC106_1: C106.1 U101.22(SS)
NetC109_2: C109.2 U101.20(REFCAP)
NetC110_1: C110.1 R111.1 U101.18(CS_ILIM)
NetC111_1: C111.1 R112.1
NetC112_1: C112.1 R112.2 U101.24(COMP)
NetC117_1: C117.1 D106.1(K) D109.2(A) Q105.3(D) T103.7
NetC117_2: C117.2 R117.2 R119.2
NetC118_1: C118.1 D107.1(K) D110.2(A) Q106.3(D) T103.11
NetC118_2: C118.2 R118.2 R120.2
NetC122_1: C122.1 D109.1(K) D110.1(K) R121.1 R301.1
NetD3_1: D3.1(K) D4.1(K) Q101.3(D) Q103.3(D) T102.2
NetD101_2: D101.2(ANODE) D103.1(CATHODE) T102.4
NetD102_1: D102.1(CATHODE) R103.2 R111.2
NetD102_2: D102.2(ANODE) D104.1(CATHODE) T102.3
NetD105_2: D105.2(A) R113.2 U101.14(SRB)
NetD108_2: D108.2(A) R114.2 U101.15(SRA)
NetD111_2: D111.2(A) L102.2 Q107.3(D)
NetD112_2: D112.2(A) L103.2 Q108.3(D)
NetD113_2: D113.2(A) L102.4 R122.2
NetD114_2: D114.2(A) L103.4 R123.2
NetFull_Bridge_Bode_2: Full_Bridge_Bode.2 R124.1 R125.2
NetL101_1: L101.1 T103.9
NetL102_1: L102.1 Q107.1(G) R115.1
NetL103_1: L103.1 Q108.1(G) R116.1
NetL301_2: L301.2 T103.5 T103.6
NetQ109_1: Q109.1(B) R122.1
NetQ110_1: Q110.1(B) R123.1
NetR101_2: R101.2 U101.2(PS)
NetR102_2: R102.2 U101.3(SP)
NetR104_1: R104.1 U101.4(LEB)
NetR105_1: R105.1 U101.1(RT)
NetR106_2: R106.2 U101.6(SYNC)
NetR109_1: R109.1 U101.19(FAULT)
NetR110_1: R110.1 U101.21(RSC)
NetR115_2: R115.2 U101.10(OUTA)
NetR116_2: R116.2 U101.11(OUTB)

Not connected (* = marked no-connect by the designer): Q101 2(G); Q102 2(G); Q103 2(G); Q104 2(G); Q105 2(G); Q106 2(G)

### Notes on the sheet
- 22-36 Vin, 28 Vnom
- 12V / 25 A max
- 2.06 Arms ripple
- (near T103) PRI : SEC = 3 : 2
- (near T103) Lpri = 22uH
- Lleak = 250nH
- Note: designators over 300 do not have silk screen labels
- Power stage
- (near 12Vp_EXT) Adding these test points to use an external 12V supply for primary and secondary 12V
- 10.61 MHz
- fp,hf = 35.3 kHz
- fp,comp = 777 Hz
- Full-bridge controller

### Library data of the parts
12V 12Vp_EXT 12Vs_EXT VIN_28V = CMP-0055147-2: Test Point, Multipurpose, Red, TH; Manufacturer: Keystone Electronics; CT: TRUE; ContactFinish: Silver; Green_Lifecycle: Active; CNHeader: FALSE; Green_REACh: Passed
12V_EN Full_Bridge_Bode = CMP-0055571-1: Header, 2mm, 3x1, Gold, TH; Manufacturer: Samtec; Current_A: 2.9A; Shrouded: N; CT: FALSE; Cert_UL: Y; Pitch_mm: 2; CNHeader: TRUE; Gender: Male
C19 C20 C107 C108 = CMP-0860266-1: CAP, CERM, 10 µF, 50 V,+/- 10%, X8L, AEC-Q200 Grade 0, 1210; Manufacturer: MuRata; Value: 10uF; U/M: EA; SizeY_mm: 2.5; Polarized: N; AEC Category: Q200; SizeZ_mm: 2.7; TaMin_C: -55°C; AEC Qualified: Y; TaMax_C: 150°C; Cap_Case: 1210; SizeArea_mm2: 8; SizeAreaWB_mm2: 14.7; AEC Grade: 0; SizeX_mm: 3.2
C101 C115 C116 = CMP-0007405-5: CAP, CERM, 1 uF, 25 V, +/- 10%, X7R, 0603; Manufacturer: MuRata; Cap_Case: 0603; AEC Category: Q200; Value: 1uF; SizeX_mm: 1.6; U/M: EA; Value1: Unknown; SizeAreaWB_mm2: 4.68; SizeY_mm: 0.8; TaMin_C: -55°C; SizeZ_mm: 1; Polarized: N; MFG_Status: TI_Obsolete; TaMax_C: 125°C; SizeArea_mm2: 1.28
C102 C103 = CMP-0011753-2: CAP, TA, 22 uF, 50 V, +/- 10%, 0.5 ohm, SMD; Manufacturer: Kemet; TaMin_C: -55°C; ESR_ohm: 0.5; Polarized: Y; SizeAreaWB_mm2: 58.59; Value1: 0.5 ohm; U/M: EA; Value: 22uF; TaMax_C: 125°C; SizeZ_mm: 4.3; SizeX_mm: 7.3; SizeArea_mm2: 31.39; CompType: Capacitor; AEC Qualified: N; Cap_F: 22µF; IRMS_A: 574mA; AEC Category: Q200
C104 = CMP-0007499-4: CAP, CERM, 2.2 uF, 16 V, +/- 10%, X7R, 0603; Manufacturer: MuRata; TaMin_C: -55°C; Polarized: N; SizeAreaWB_mm2: 4.68; Value1: Unknown; U/M: EA; Value: 2.2uF; TaMax_C: 125°C; SizeZ_mm: 1; SizeX_mm: 1.6; SizeY_mm: 0.8; Cap_Case: 0603; SizeArea_mm2: 1.28; AEC Category: Q200
C105 = CMP-0007425-5: CAP, CERM, 5600 pF, 25 V, +/- 10%, X7R, 0603; Manufacturer: MuRata; ValueDisplayed: 5600pF; SizeArea_mm2: 1.28; SizeZ_mm: 1; Value2: 25V; MFG_Status: TI_Obsolete; SizeX_mm: 1.6; Value1: Unknown; AEC Category: Q200; Value: 5600pF; SizeAreaWB_mm2: 4.68; Polarized: N; Cap_Case: 0603; U/M: EA; TaMin_C: -55°C; TaMax_C: 125°C; SizeY_mm: 0.8
C106 = CMP-0084679-1: CAP, CERM, 0.1 µF, 25 V,+/- 10%, X7R, AEC-Q200 Grade 1, 0603; Manufacturer: MuRata; VDC_V: 25V; TaMin_C: -55°C; SizeY_mm: 0.8; Polarized: N; SizeArea_mm2: 1.28; Cap_Case: 0603; SizeZ_mm: 1; SizeX_mm: 1.6; AEC Qualified: Y; AEC Category: Q200; ValueDisplayed: 0.1µF; TaMax_C: 125°C; U/M: EA; SizeAreaWB_mm2: 4.68; Cap_F: 100nF
C109 = CMP-0007138-4: as C54 on sheet 12V Bias
C110 = CMP-0084283-1: CAP, CERM, 10 pF, 100 V,+/- 5%, C0G/NP0, AEC-Q200 Grade 1, 0603; Manufacturer: MuRata; TaMax_C: 125°C; Cap_Case: 0603; Value2: 100V; SizeX_mm: 1.6; SizeY_mm: 0.8; SizeArea_mm2: 1.28; Polarized: N; AEC Category: Q200; SizeAreaWB_mm2: 4.68; AEC Qualified: Y; SizeZ_mm: 1; Value: 10pF; U/M: EA; TaMin_C: -55°C
C111 = CMP-0007427-5: CAP, CERM, 6800 pF, 25 V, +/- 10%, X7R, 0603; Manufacturer: MuRata; Value1: Unknown; MFG_Status: TI_Obsolete; SizeY_mm: 0.8; TaMin_C: -55°C; Value2: 25V; U/M: EA; SizeAreaWB_mm2: 4.68; SizeArea_mm2: 1.28; AEC Category: Q200; SizeZ_mm: 1; ValueDisplayed: 6800pF; Polarized: N; SizeX_mm: 1.6; TaMax_C: 125°C; Cap_Case: 0603; Value: 6800pF
C112 = CMP-0007179-4: CAP, CERM, 120 pF, 50 V, +/- 5%, C0G/NP0, 0603; Manufacturer: MuRata; TaMin_C: -55°C; Polarized: N; SizeAreaWB_mm2: 4.68; Value1: Unknown; U/M: EA; Value: 120pF; TaMax_C: 125°C; SizeZ_mm: 1; SizeX_mm: 1.6; SizeY_mm: 0.8; Cap_Case: 0603; Value2: 50V; SizeArea_mm2: 1.28; AEC Category: Q200
C113 C114 = CMP-0007171-4: CAP, CERM, 100 pF, 50 V, +/- 5%, C0G/NP0, 0603; Manufacturer: MuRata; TaMin_C: -55°C; Polarized: N; SizeAreaWB_mm2: 4.68; Value1: Unknown; U/M: EA; Value: 100pF; TaMax_C: 125°C; SizeZ_mm: 1; SizeX_mm: 1.6; SizeY_mm: 0.8; Cap_Case: 0603; Value2: 50V; SizeArea_mm2: 1.28; AEC Category: Q200
C117 C118 = CMP-0008098-2: CAP, CERM, 1200 pF, 100 V, +/- 5%, C0G/NP0, 0805; Manufacturer: MuRata; TaMin_C: -55°C; Polarized: N; SizeAreaWB_mm2: 6.75; Value1: Unknown; U/M: EA; Value: 1200pF; TaMax_C: 125°C; SizeZ_mm: 1.45; SizeX_mm: 2; SizeY_mm: 1.25; Cap_Case: 0805; SizeArea_mm2: 2.5; Cap_F: 1.2nF; AEC Category: Q200
C119 C120 = CMP-0082252-1: CAP, CERM, 10 µF, 25 V,+/- 20%, X7R, AEC-Q200 Grade 1, 1206; Manufacturer: MuRata; SizeAreaWB_mm2: 10.92; SizeArea_mm2: 5.12; AEC Qualified: Y; AEC Category: Q200; Value: 10uF; TaMax_C: 125°C; SizeZ_mm: 1.35; AEC Grade: 1; Polarized: N; TaMin_C: -55°C; SizeY_mm: 1.6; U/M: EA; SizeX_mm: 3.2
C121 C123-C125 = CMP-0012041-2: CAP, TA, 100 uF, 25 V, +/- 10%, 0.1 ohm, SMD; Manufacturer: AVX; TaMin_C: -55°C; ESR_ohm: 0.1; Polarized: Y; SizeAreaWB_mm2: 75.33; Value1: 0.1 ohm; U/M: EA; Value: 100uF; TaMax_C: 125°C; SizeZ_mm: 3.8; SizeX_mm: 7.3; SizeY_mm: 6.1; SizeArea_mm2: 44.53; CompType: Capacitor; Cap_F: 100µF; IRMS_A: 1.423A; AEC Category: Q200
C122 = CMP-0008881-2: CAP, CERM, 0.1 uF, 100 V, +/- 10%, X7R, 1206; Manufacturer: MuRata; TaMin_C: -55°C; Polarized: N; SizeAreaWB_mm2: 10.92; Value1: Unknown; U/M: EA; Value: 0.1uF; TaMax_C: 125°C; SizeZ_mm: 1.35; SizeX_mm: 3.2; SizeY_mm: 1.6; SizeArea_mm2: 5.12; Cap_F: 100nF; AEC Category: Q200
C301-C304 = CMP-0008346-3: CAP, CERM, 4.7 uF, 25 V, +/- 10%, X7R, 0805; Manufacturer: MuRata; TaMax_C: 125°C; SizeZ_mm: 1.45; Value1: Unknown; Polarized: N; SizeY_mm: 1.25; TaMin_C: -55°C; SizeX_mm: 2; SizeAreaWB_mm2: 6.75; MFG_Status: TI_Obsolete; SizeArea_mm2: 2.5; AEC Category: Q200; Cap_Case: 0805; Value: 4.7uF; U/M: EA
D3 D4 D9 D10 D106 D107 D109 D110 = CMP-0028521-2: Diode, Schottky, 100 V, 1 A, SMB; Manufacturer: ON Semiconductor; TJmax_C: 150°C; SizeY_mm: 3.81; RJC_CperW: 22; Value1: 1A; SizeAreaWB_mm2: 44.156; Green_Lifecycle: Active; SizeArea_mm2: 21.336; Vf_V: 750mV; SizeZ_mm: 2.6; SizeX_mm: 5.6; Green_REACh: Passed; Value2: 0.75V; AEC Category: Q101
D101-D104 = CMP-0090343-1: Diode Schottky 100V 250mA (DC) Surface Mount SOD-123; Manufacturer: Nexperia; SizeZ_mm: 1.3mm; Peak Reverse Current: 2uA; TaMin_C: -55°C; Cap_F: 39pF; TJmax_C: 150°C; AEC Grade: Grade 0; Max Surge Forward Current: 2.5A; Standoff Height: 0mm; TaMax_C: +150°C; AEC Qualified: Yes
D105 D108 D111 D112 = CMP-0080763-2: Diode, Schottky, 40 V, 3 A, AEC-Q101, SOD-123W; Manufacturer: Nexperia; Value2: 0.54V; AEC Category: Q101; SizeArea_mm2: 5.95; AEC Qualified: Y; Io_A: 3A; SizeZ_mm: 1; Value: 40V; SizeY_mm: 1.7; Vf_V: 540mV; SizeAreaWB_mm2: 12.15; SizeX_mm: 3.5; TJmax_C: 150°C
D113 D114 = CMP-0076974-2: Diode, Switching, 100 V, 0.15 A, SOD-123; Manufacturer: Micro Commercial Components; Io_A: 150mA; SizeX_mm: 3.85; SizeY_mm: 1.7; Green_REACh: Incomplete; AEC Category: Q101; TJmax_C: 150°C; Value1: 0.15A; Vf_V: 1.25V; Value: 100V; SizeZ_mm: 1.35; SizeArea_mm2: 6.545; SizeAreaWB_mm2: 13.095; Green_Lifecycle: Not Set
L101 = CMP-0064040-1: Inductor, Shielded Drum Core, WE-Superflux200, 1.3 uH, 34.5 A, 0.0009 ohm, SMD; Manufacturer: Wurth Elektronik; Isat: 62A @ 30% inductance drop; Irms: 34.5A @ 50C rise; Green_Lifecycle: Active; SizeAreaWB_mm2: 410.06; DCR_ohm: 900µ; Green_REACh: Passed; Value: 1.3uH; Imax_A: 34.5A; SizeZ_mm: 9.2; SizeX_mm: 18.3; SizeY_mm: 18.2; SizeArea_mm2: 333.06; Ind_H: 1.3µH; AEC Category: Q200
L102 L103 = CMP-0012812-2: Coupled inductor, 22 uH, 0.7 A, 1.63 ohm, TH; Manufacturer: Coilcraft; SizeAreaWB_mm2: 25; DCR_ohm: 1.63; Value: 22uH; SizeZ_mm: 1.2; SizeX_mm: 4; SizeArea_mm2: 16; Ind_H: 22µH
L301 = CMP-0125020-1: Air Core Inductor, High Current, 117 nH, 44 A, 1212VS Series, ± 20%, 0.00143 ohm, 399 MHz; Manufacturer: Coilcraft; AEC Qualified: No; DCR_ohm: 1.43m; Irms: 44A; SizeZ_mm: 11.3mm; Q Factor: 165; Self Resonant Frequency: 399MHz; TaMax_C: +125°C; TaMin_C: -40°C; Test Frequency: 1MHz
PGND_1 SGND_1 = CMP-0055148-2: Test Point, Multipurpose, Black, TH; Manufacturer: Keystone Electronics; CNHeader: FALSE; ContactFinish: Silver; Green_REACh: Passed; Green_Lifecycle: Active; CT: TRUE
Q101-Q106 = CMP-0047628-1: MOSFET N-Channel 100 V 80A (Tc) Surface Mount 5-SMD; Manufacturer: EPC Space; AEC Qualified: No; QgTyp_nC: 11.7nC @ 5V; Rdson45_ohm: 5.2m; SizeZ_mm: 2.235mm; Vgs_V: 6V; ChMode: False; Input Capacitace At Vds: 1240pF @ 50V; Number Of Channels: 1; Pulse Drain Current: 345A; Rthja Max: 48°C/W; Threshold Vgs Max: 2.5V; Threshold Vgs Min: 0.8V; TJmax_C: +150°C
Q107 Q108 = CMP-0000755-1: MOSFET, N-CH, 50 V, 0.22 A, SOT-23; Alternate Manufacturer: None; Manufacturer: Fairchild Semiconductor; SizeZ_mm: 1.1; ChType: N; Value2: 1.7 nC; VdsMax_V: 50V; SizeX_mm: 2.5; SizeY_mm: 3; Vgs_V: 20V; Value: 50V; Rdson45_ohm: 6; SizeArea_mm2: 7.5; AEC Category: Q101; IdsMax_A: 220mA; SizeAreaWB_mm2: 14; U/M: EA; QgTyp_nC: 1.7
Q109 Q110 = CMP-0000331-2: Transistor, PNP, 60 V, 0.8 A, SOT-23; Manufacturer: Fairchild Semiconductor; TaMax_C: 150°C; Value2: 300; Value1: 0.8 A; Vcesat1_V: 1.6V; SizeX_mm: 2.5; SizeY_mm: 3; TaMin_C: -55°C; IcRated_A: 800mA; CompType: BJT; SizeZ_mm: 1.1; Value: 60 V; SizeArea_mm2: 7.5; NPN: 0; Vceo_V: 60V; PNP: 1; AEC Category: Q101; SizeAreaWB_mm2: 14; U/M: EA
R1 R2 = CMP-0095678-1: 4 mOhms ±1% 1W Chip Resistor Wide 0805 (2012 Metric), 0508 Automotive AEC-Q200, Current Sense Metal Foil; Manufacturer: Susumu; TempCo: 50ppm/°C; SizeZ_mm: 0.7mm; AEC Qualified: Yes; AEC Grade: Grade 0
R76 R104 = CMP-0022447-4: as R46 on sheet 12V Bias
R101 = CMP-0022052-4: RES, 147 k, 1%, 0.1 W, AEC-Q200 Grade 0, 0603; Manufacturer: Vishay-Dale; Power_W: 100mW; TempCo: 100 ppm/C; Value: 147k; EIA_Code: E96; SizeX_mm: 1.6; SizeY_mm: 0.8; SizeZ_mm: 1; Value2: 0.1W; SizeArea_mm2: 1.28; AEC Qualified: Y; VDC_V: 75V; AEC Category: Q200; AEC Grade: 0
R102 = CMP-0022589-4: as R47 on sheet 12V Bias
R103 = CMP-0016768-3: RES, 1.69, 1%, 0.25 W, AEC-Q200 Grade 0, 1206; Manufacturer: Vishay-Dale; Power_W: 250mW; TempCo: 100 ppm/C; Value_Code: 1R69; Value: 1.69; EIA_Code: E96; SizeX_mm: 3.2; SizeY_mm: 1.6; SizeZ_mm: 1.35; Value2: 0.25W; SizeArea_mm2: 5.12; AEC Qualified: Y; VDC_V: 200V; AEC Category: Q200; AEC Grade: 0
R105 = CMP-0022903-4: RES, 205 k, 1%, 0.1 W, 0603; Manufacturer: Yageo; Power_W: 100mW; TempCo: 100 ppm/C; Value: 205k; EIA_Code: E96; SizeX_mm: 1.6; SizeY_mm: 0.8; SizeZ_mm: 1; Value2: 0.1W; SizeArea_mm2: 1.28; AEC Qualified: N; VDC_V: 75V; AEC Category: Q200; SizeAreaWB_mm2: 4.68
R106 = CMP-0025736-4: RES, 1.0 M, 5%, 0.1 W, AEC-Q200 Grade 0, 0603; Manufacturer: Vishay-Dale; Power_W: 100mW; TempCo: 200 ppm/C; Value_Code: 1M00; Value: 1.0Meg; EIA_Code: E24; Res_ohm: 1M; SizeX_mm: 1.6; SizeY_mm: 0.8; SizeZ_mm: 1; Value2: 0.1W; SizeArea_mm2: 1.28; AEC Qualified: Y; VDC_V: 75V; AEC Category: Q200; AEC Grade: 0
R107 R109 = CMP-0025697-4: as R77 on sheet 12V Bias
R110 = CMP-0022347-4: RES, 34.8 k, 1%, 0.1 W, AEC-Q200 Grade 0, 0603; Manufacturer: Vishay-Dale; Power_W: 100mW; TempCo: 100 ppm/C; Value_Code: 34k8; Value: 34.8k; EIA_Code: E96; SizeX_mm: 1.6; SizeY_mm: 0.8; SizeZ_mm: 1; Value2: 0.1W; SizeArea_mm2: 1.28; AEC Qualified: Y; VDC_V: 75V; AEC Category: Q200; AEC Grade: 0
R111 = CMP-0022126-4: RES, 1.50 k, 1%, 0.1 W, AEC-Q200 Grade 0, 0603; Manufacturer: Vishay-Dale; Power_W: 100mW; TempCo: 100 ppm/C; Value_Code: 1k50; Value: 1.50k; EIA_Code: E96; Res_ohm: 1.5k; SizeX_mm: 1.6; SizeY_mm: 0.8; SizeZ_mm: 1; Value2: 0.1W; SizeArea_mm2: 1.28; AEC Qualified: Y; VDC_V: 75V; AEC Category: Q200; AEC Grade: 0
R112 = CMP-0022324-4: RES, 30.1 k, 1%, 0.1 W, AEC-Q200 Grade 0, 0603; Manufacturer: Vishay-Dale; Power_W: 100mW; TempCo: 100 ppm/C; Value_Code: 30k1; Value: 30.1k; EIA_Code: E96; SizeX_mm: 1.6; SizeY_mm: 0.8; SizeZ_mm: 1; Value2: 0.1W; SizeArea_mm2: 1.28; AEC Qualified: Y; VDC_V: 75V; AEC Category: Q200; AEC Grade: 0
R113 R114 = CMP-0025700-4: RES, 100, 5%, 0.1 W, AEC-Q200 Grade 0, 0603; Manufacturer: Vishay-Dale; Power_W: 100mW; TempCo: 200 ppm/C; Value_Code: 100R; Value: 100; EIA_Code: E24; SizeX_mm: 1.6; SizeY_mm: 0.8; SizeZ_mm: 1; Value2: 0.1W; SizeArea_mm2: 1.28; AEC Qualified: Y; VDC_V: 75V; AEC Category: Q200; AEC Grade: 0
R115 R116 = CMP-0020803-2: RES, 0, 5%, 0.125 W, 0805; Manufacturer: Yageo America; Power_W: 125mW; TempCo: 200 ppm/C; Value_Code: 0000; U/M: EA; Value: 0; EIA_Code: E24; SizeX_mm: 2; SizeY_mm: 1.25; SizeZ_mm: 1.45; Value2: 0.125W; SizeArea_mm2: 2.5; VDC_V: 150V; AEC Category: Q200
R117-R120 = CMP-0015945-3: RES, 33, 5%, 1 W, AEC-Q200 Grade 0, 2512; Manufacturer: Vishay-Dale; Power_W: 1W; TempCo: 200 ppm/C; Value_Code: 33R0; Value: 33; EIA_Code: E24; SizeX_mm: 6.3; SizeY_mm: 3.2; SizeZ_mm: 0.71; SizeArea_mm2: 20.16; AEC Qualified: Y; VDC_V: 500V; AEC Grade: 0; AEC Category: Q200
R121 R301 = CMP-0122385-1: 10 kOhms ±1% 2W Chip Resistor 2512 (6432 Metric) Current Sense Thick Film; Manufacturer: Bourns; AEC Qualified: No; SizeZ_mm: 0.8mm; TempCo: 100ppm/°C; VDC_V: 300V
R122 R123 = CMP-0021998-4: as R50 on sheet 12V Bias
R124 = CMP-0022003-4: RES, 10.0, 1%, 0.1 W, AEC-Q200 Grade 0, 0603; Manufacturer: Vishay-Dale; Power_W: 100mW; TempCo: 100 ppm/C; Value_Code: 10R0; Value: 10.0; EIA_Code: E96; Res_ohm: 10; SizeX_mm: 1.6; SizeY_mm: 0.8; SizeZ_mm: 1; Value2: 0.1W; SizeArea_mm2: 1.28; AEC Qualified: Y; VDC_V: 75V; AEC Category: Q200; AEC Grade: 0
R125 = CMP-0022012-4: RES, 115 k, 1%, 0.1 W, AEC-Q200 Grade 0, 0603; Manufacturer: Vishay-Dale; Power_W: 100mW; TempCo: 100 ppm/C; Value: 115k; EIA_Code: E96; SizeX_mm: 1.6; SizeY_mm: 0.8; SizeZ_mm: 1; Value2: 0.1W; SizeArea_mm2: 1.28; AEC Qualified: Y; VDC_V: 75V; AEC Category: Q200; AEC Grade: 0
R126 = CMP-0022559-4: as R66 on sheet 12V Bias
T102 = CMP-0122471-1: Current Transformer 1:50; Manufacturer: Payton Planar; SizeZ_mm: 9mm; AEC Qualified: No
T103 = CMP-0122726-1: Transformer Vin-22-36V/500KHz/Full-Bridge, Vo=12V/26A Isolation=1500V, T/R=3:2; Manufacturer: Coilcraft; Ind_H: 22µH; Ns1toNp: 3:2; SizeZ_mm: 17.04mm; AEC Qualified: No; Voltage_Isolation_Vrms: 1.5kV
U101 = CMP-0092938-1: Manufacturer: Texas Instruments; AEC Qualified: No; SizeZ_mm: 1.2mm; Standoff Height: 0.05mm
